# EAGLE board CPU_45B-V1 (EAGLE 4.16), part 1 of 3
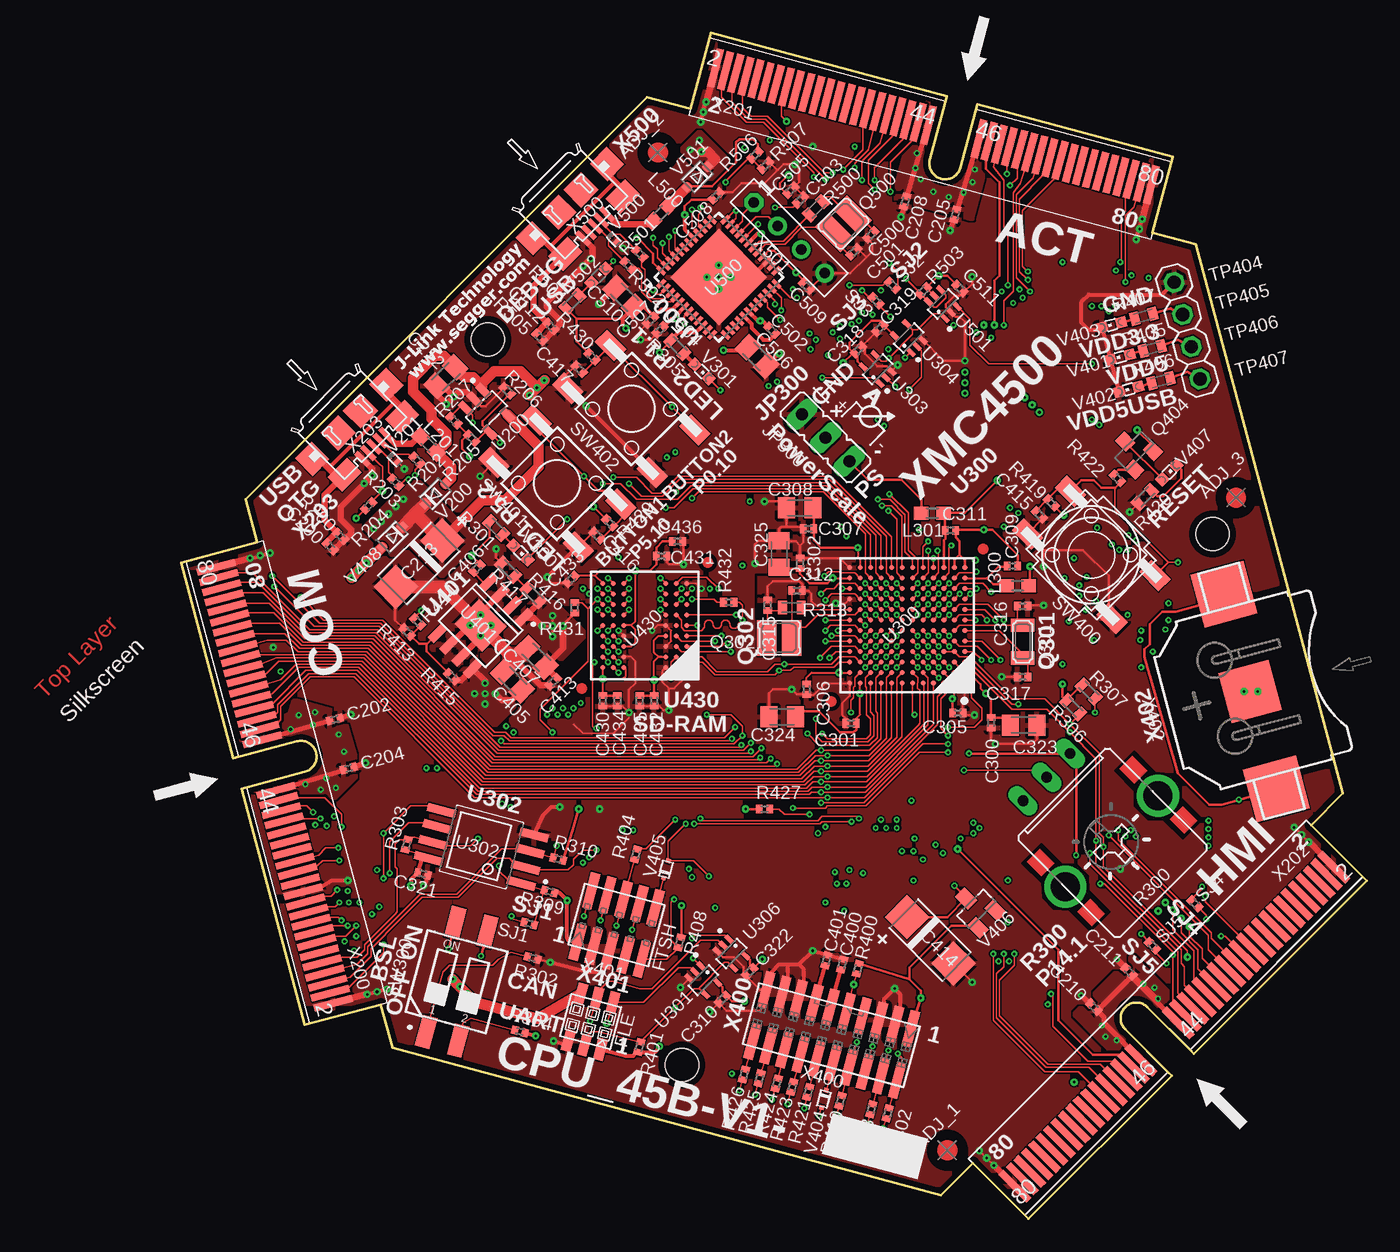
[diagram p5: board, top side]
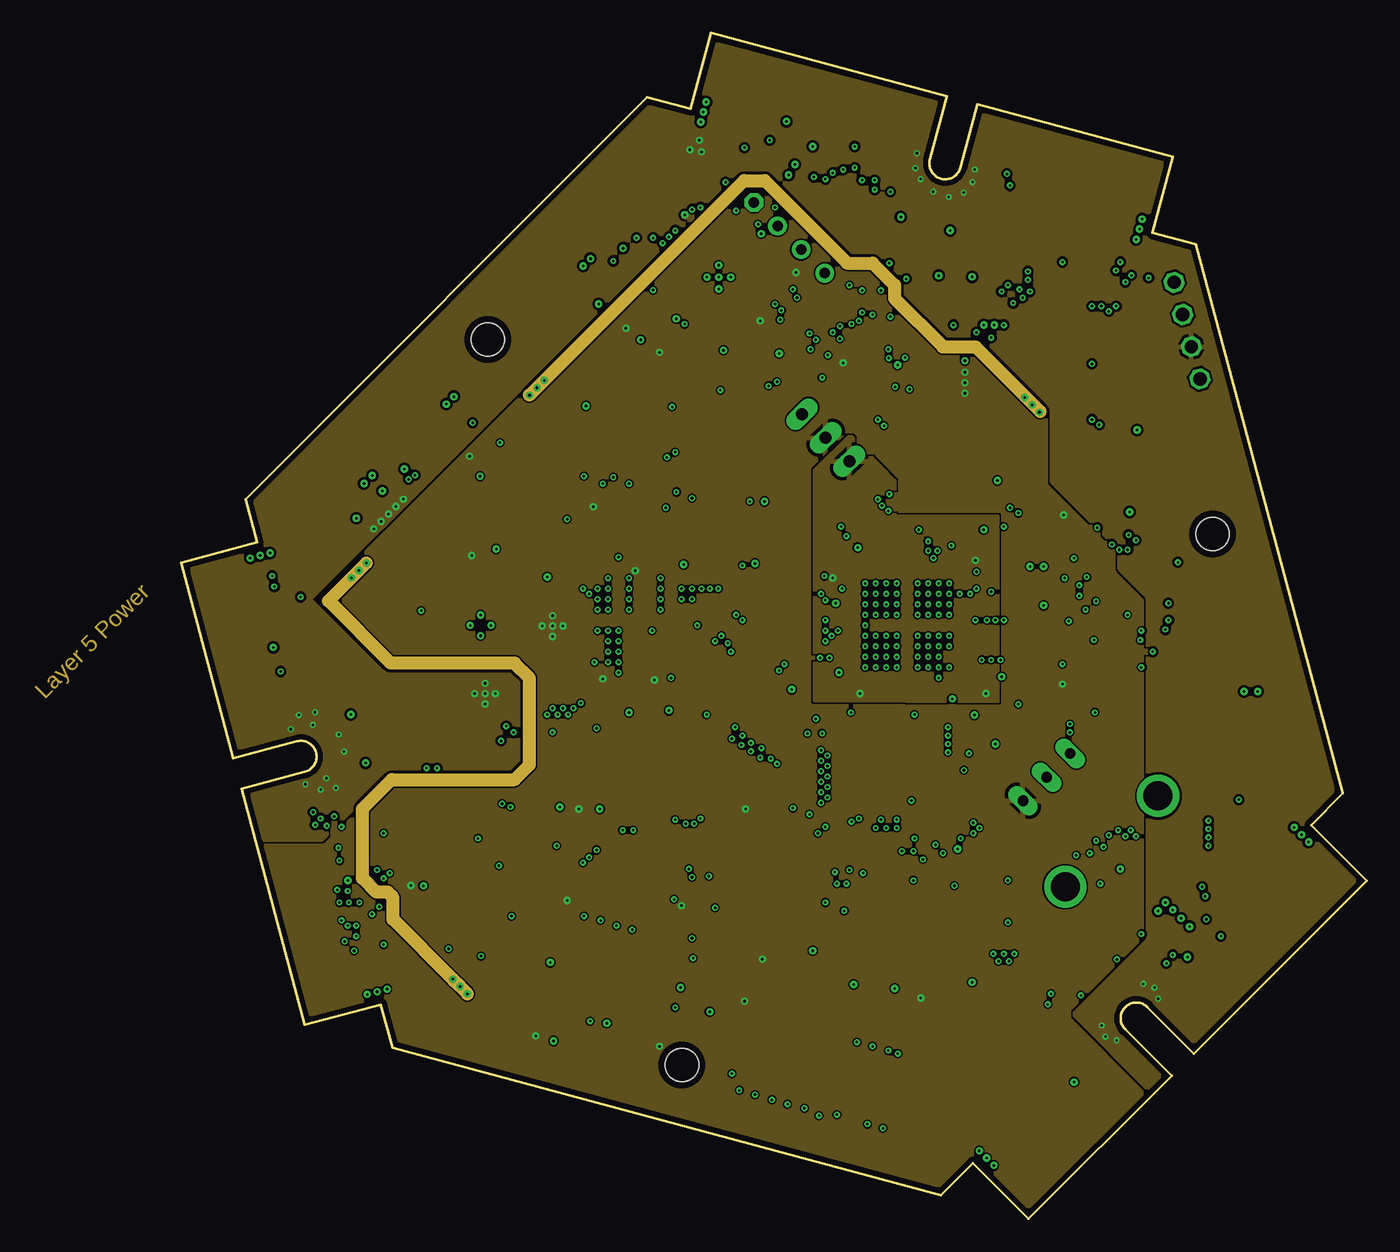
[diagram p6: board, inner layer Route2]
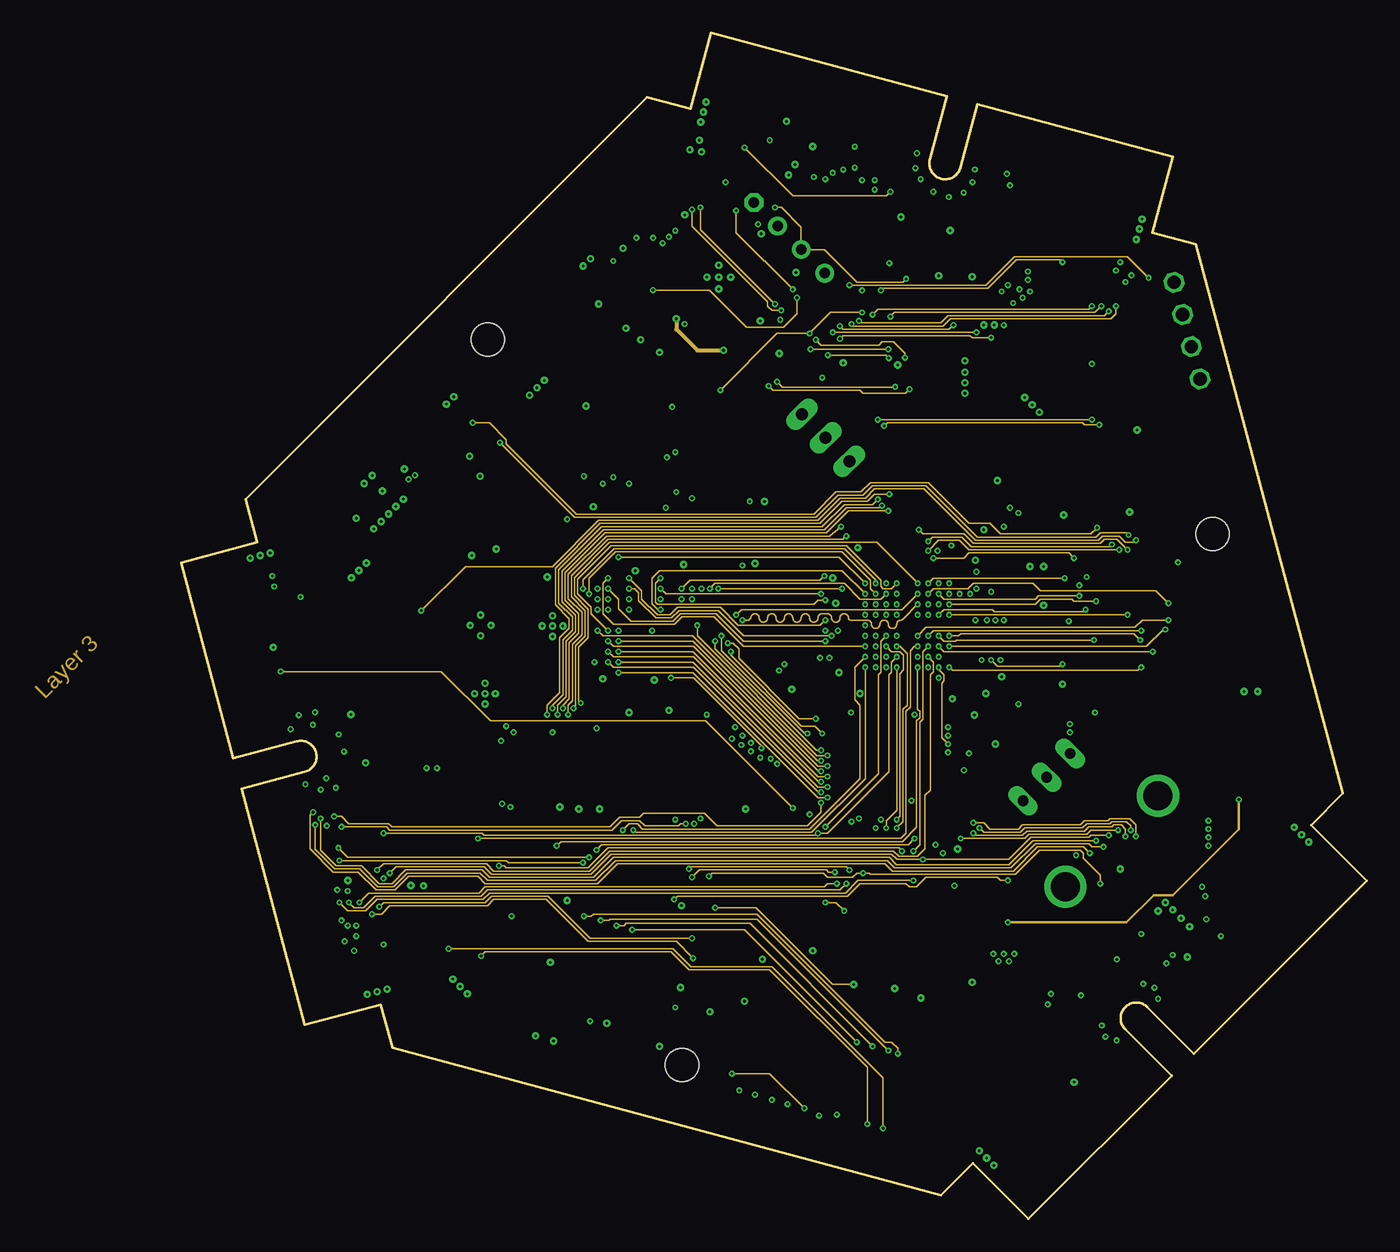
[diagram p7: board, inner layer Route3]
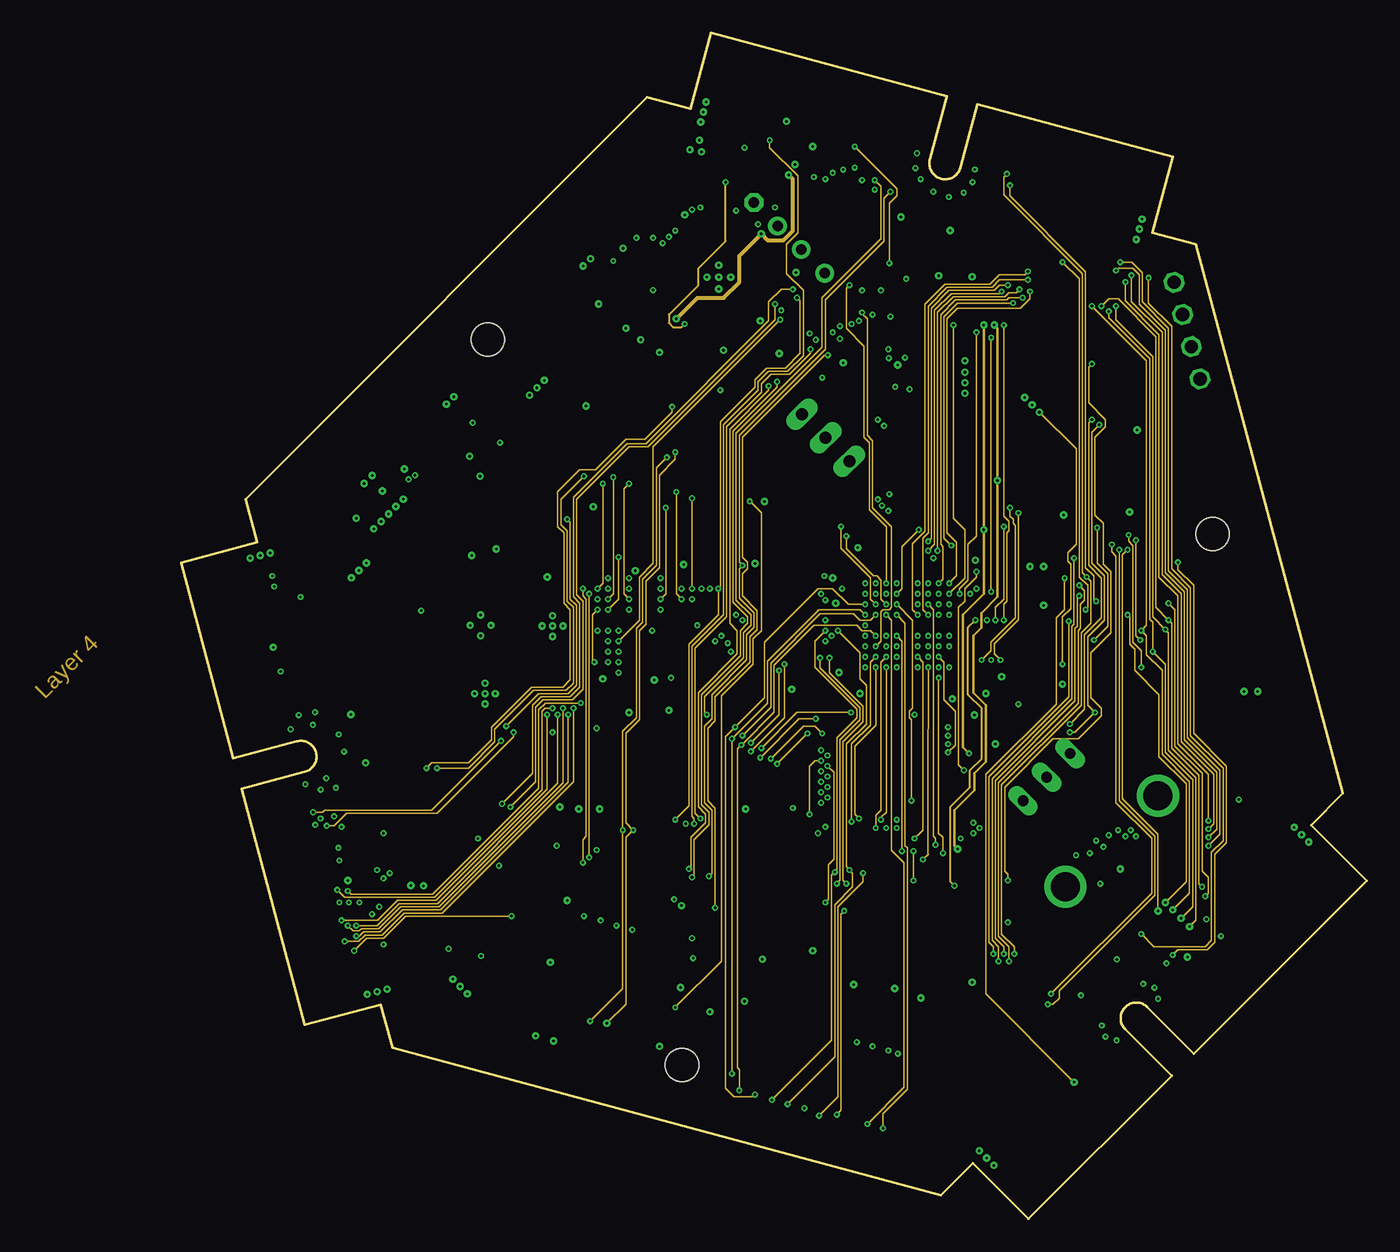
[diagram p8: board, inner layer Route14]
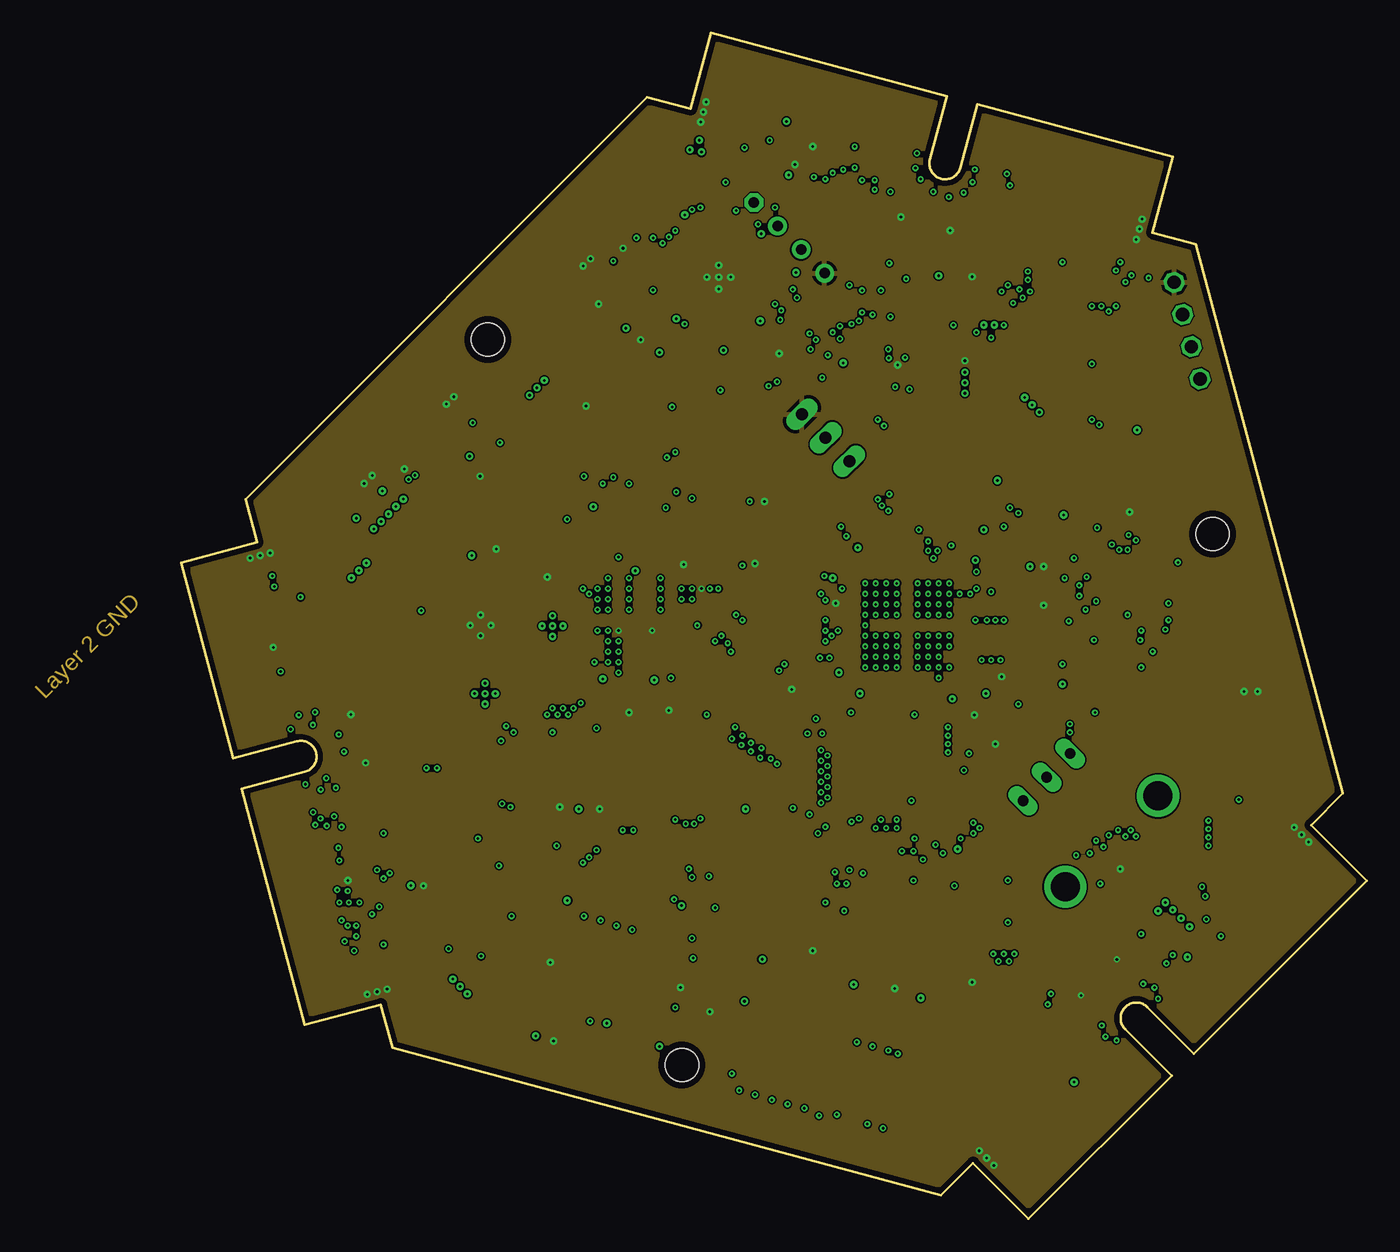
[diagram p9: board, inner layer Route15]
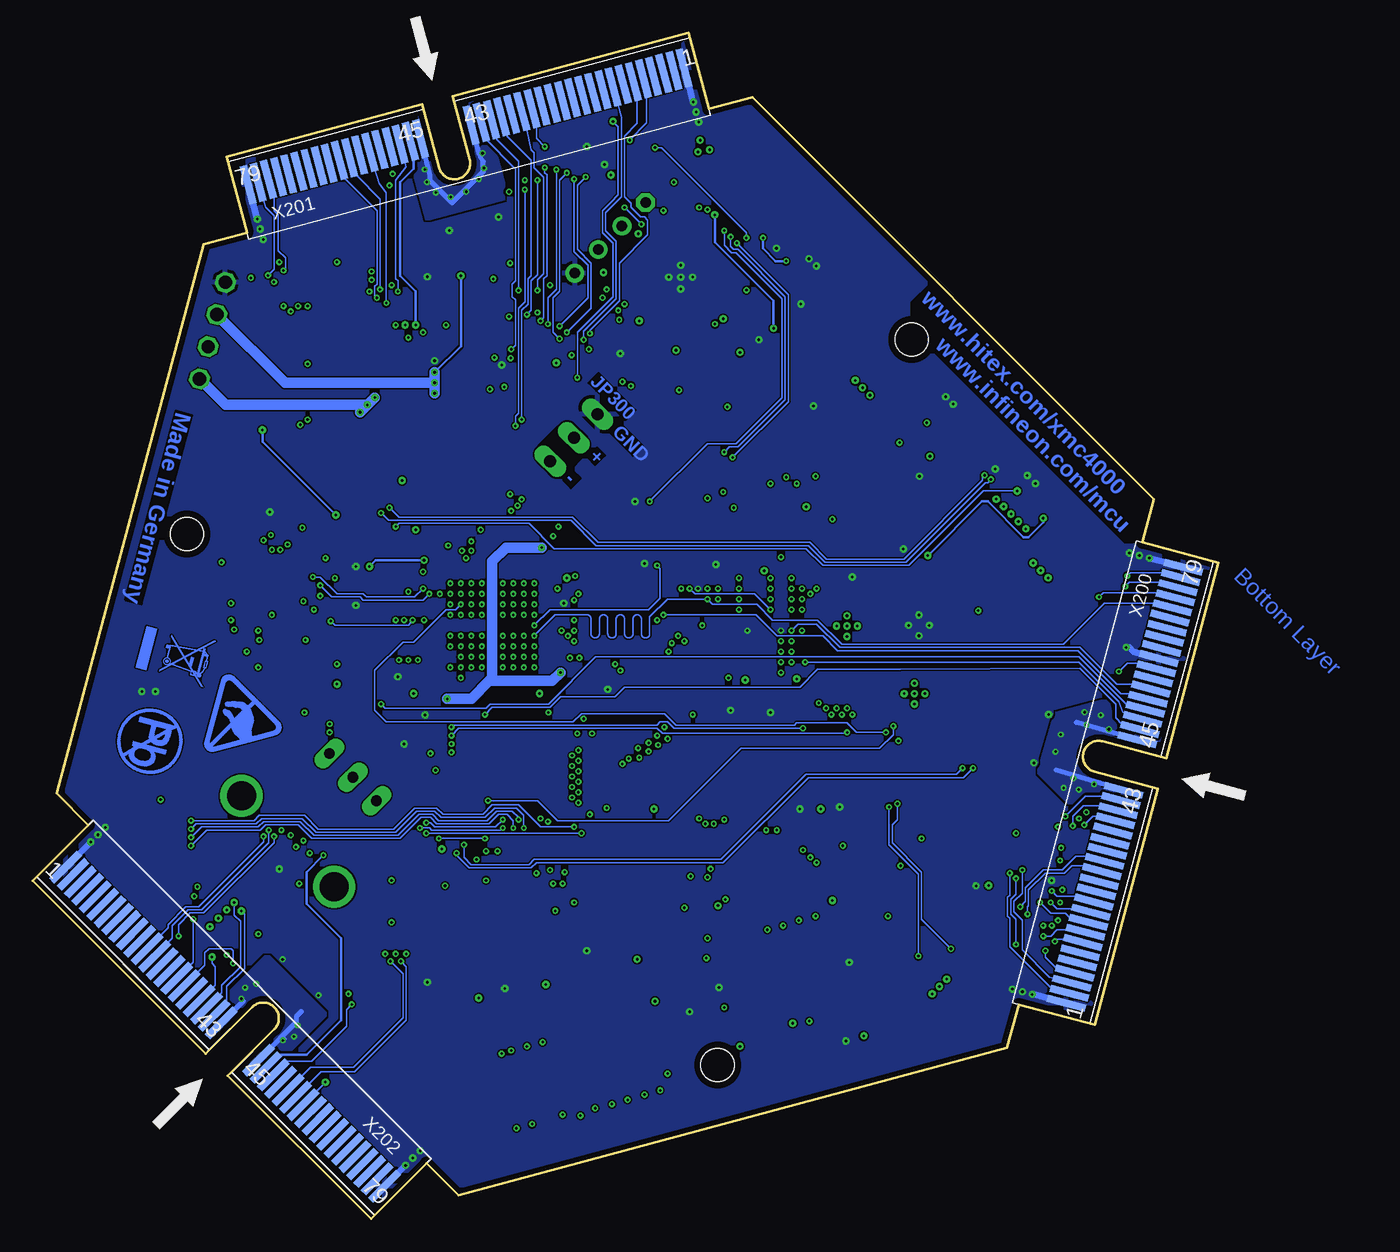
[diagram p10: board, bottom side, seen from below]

Size 90.38 x 90.38 mm. Coordinates in mm from the lower left corner, seen from the top.
Outline: 15.23,16.34 16.12,13.03 57.94,1.82 60.36,4.24
Outline: 5.79,51.54 4.91,54.85 35.53,85.47 38.84,84.58
Outline: 74.04,75.15 77.35,74.26 88.56,32.44 86.14,30.02
Copper layers (1*2+3*14+15*16): Top 0.035mm / dielectric 0.27mm / Route2 0.035mm / dielectric 0.27mm / Route3 0.035mm / dielectric 0.27mm / Route14 0.035mm / dielectric 0.27mm / Route15 0.035mm / dielectric 0.27mm / Bottom 0.035mm
Design rules "default": minimum track width 0.12mm, minimum drill 6mil, track to track 0.119mm, track to pad 0.12mm, pad to pad 0.12mm, via to via 0.12mm, smd to smd 5mil, copper to edge 0.5mm, drill to drill 8mil, minimum pad ring 10mil, minimum via ring 0.125mm, stop-mask expansion 4mil, vias tented up to drill 0.2mm, thermal gap 10mil
Holes 2.54 mm at 23.38,67 38.19,11.74 78.64,52.19
tRestrict: 2 lines
bRestrict: 6 lines
Milling: 9 lines

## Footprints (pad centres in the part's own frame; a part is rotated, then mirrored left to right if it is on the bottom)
C0402 = smd 0.5 x 0.65: 1 -0.4,0; 2 0.4,0
C0805K = smd 1.3 x 1.6: 1 -1,0; 2 1,0
SMC_C = smd 2.4 x 2.4: + -2.5,0; - 2.5,0
PS3_MIRROR_SW = drill 0.914 long: 1 0,0; 2 2.54,0; 3 -2.54,0
L1608 = smd 1.1 x 1: 1 -0.85,0; 2 0.85,0
FC-135 = smd 1 x 1.8: P$1 -1.25,0; P$2 1.25,0
32X25_2PAD = smd 1.5 x 2.7: 1 -0.95,0; 2 0.95,0
TO236 = smd 1 x 1.2: 1 -1,-1; 2 1,-1; 3 0,1
R0402 = smd 0.5 x 0.65: 1 -0.4,0; 2 0.4,0
POTI = drill 0.813 long: A -2.54,-6.992; E 2.54,-6.992; S 0,-6.992 | drill 2.2 round: P$1 -5,0.025; P$2 4.9,-0.075
R0603 = smd 0.67 x 1: 1 -0.715,0; 2 0.715,0
CTS-219-02 = smd 1.13 x 2.44: 1 -1.27,-4.3; 2 1.27,-4.3; 3 1.27,4.3; 4 -1.27,4.3
FSM2JSMA = smd 2.1 x 1.3: P -4.55,-2.3; P1 4.55,-2.3; S -4.55,2.3; S1 4.55,2.3
1X01 = drill 1.016 octagon: 1 0,0
SOT23-5L = smd 0.55 x 1.2: 1 -0.95,-1.3; 2 0,-1.3; 3 0.95,-1.3; 4 0.95,1.3; 5 -0.95,1.3
P/PG-LFBGA-144-9 = smd 0.37 x 0.37: A1 -4.4,4.4; A2 -3.6,4.4; A3 -2.8,4.4; A4 -2,4.4; A5 -1.2,4.4; A6 -0.4,4.4; A7 0.4,4.4; A8 1.2,4.4; A9 2,4.4; A10 2.8,4.4; A11 3.6,4.4; A12 4.4,4.4; B1 -4.4,3.6; B2 -3.6,3.6; B3 -2.8,3.6; B4 -2,3.6; B5 -1.2,3.6; B6 -0.4,3.6; B7 0.4,3.6; B8 1.2,3.6; B9 2,3.6; B10 2.8,3.6; B11 3.6,3.6; B12 4.4,3.6; C1 -4.4,2.8; C2 -3.6,2.8; C3 -2.8,2.8; C4 -2,2.8; C5 -1.2,2.8; C6 -0.4,2.8; C7 0.4,2.8; C8 1.2,2.8; C9 2,2.8; C10 2.8,2.8; C11 3.6,2.8; C12 4.4,2.8; D1 -4.4,2; D2 -3.6,2; D3 -2.8,2; D4 -2,2; D5 -1.2,2; D6 -0.4,2; D7 0.4,2; D8 1.2,2; D9 2,2; D10 2.8,2; D11 3.6,2; D12 4.4,2; E1 -4.4,1.2; E2 -3.6,1.2; E3 -2.8,1.2; E4 -2,1.2; E5 -1.2,1.2; E6 -0.4,1.2; E7 0.4,1.2; E8 1.2,1.2; E9 2,1.2; E10 2.8,1.2; E11 3.6,1.2; E12 4.4,1.2; F1 -4.4,0.4; F2 -3.6,0.4; F3 -2.8,0.4; F4 -2,0.4; F5 -1.2,0.4; F6 -0.4,0.4; F7 0.4,0.4; F8 1.2,0.4; F9 2,0.4; F10 2.8,0.4; F11 3.6,0.4; F12 4.4,0.4; G1 -4.4,-0.4; G2 -3.6,-0.4; G3 -2.8,-0.4; G4 -2,-0.4; G5 -1.2,-0.4; G6 -0.4,-0.4; G7 0.4,-0.4; G8 1.2,-0.4; G9 2,-0.4; G10 2.8,-0.4; G11 3.6,-0.4; G12 4.4,-0.4; H1 -4.4,-1.2; H2 -3.6,-1.2; H3 -2.8,-1.2; H4 -2,-1.2; H5 -1.2,-1.2; H6 -0.4,-1.2; H7 0.4,-1.2; H8 1.2,-1.2; H9 2,-1.2; H10 2.8,-1.2; H11 3.6,-1.2; H12 4.4,-1.2; J1 -4.4,-2; J2 -3.6,-2; J3 -2.8,-2; J4 -2,-2; J5 -1.2,-2; J6 -0.4,-2; J7 0.4,-2; J8 1.2,-2; J9 2,-2; J10 2.8,-2; J11 3.6,-2; J12 4.4,-2; K1 -4.4,-2.8; K2 -3.6,-2.8; K3 -2.8,-2.8; K4 -2,-2.8; K5 -1.2,-2.8; K6 -0.4,-2.8; K7 0.4,-2.8; K8 1.2,-2.8; K9 2,-2.8; K10 2.8,-2.8; K11 3.6,-2.8; K12 4.4,-2.8; L1 -4.4,-3.6; L2 -3.6,-3.6; L3 -2.8,-3.6; L4 -2,-3.6; L5 -1.2,-3.6; L6 -0.4,-3.6; L7 0.4,-3.6; L8 1.2,-3.6; L9 2,-3.6; L10 2.8,-3.6; L11 3.6,-3.6; L12 4.4,-3.6; M1 -4.4,-4.4; M2 -3.6,-4.4; M3 -2.8,-4.4; M4 -2,-4.4; M5 -1.2,-4.4; M6 -0.4,-4.4; M7 0.4,-4.4; M8 1.2,-4.4; M9 2,-4.4; M10 2.8,-4.4; M11 3.6,-4.4; M12 4.4,-4.4
SC70-5L = smd 0.35 x 0.8: 1 -0.65,-0.85; 2 0,-0.85; 3 0.65,-0.85; 4 0.65,0.85; 5 -0.65,0.85
SO08W = smd 2.2 x 0.635: 1 -3.651,1.905; 2 -3.651,0.635; 3 -3.651,-0.635; 4 -3.651,-1.905; 5 3.651,-1.905; 6 3.651,-0.635; 7 3.651,0.635; 8 3.651,1.905
PG-DSO-8-27_NO-PASTE = smd 0.65 x 1.51: 1 -1.905,-2.745; 2 -0.635,-2.745; 3 0.635,-2.745; 4 1.905,-2.745; 5 1.905,2.745; 6 0.635,2.745; 7 -0.635,2.745; 8 -1.905,2.745 | smd 3 x 2.65: 9 0,0
VFBGA54-6X9_8MMX8MM = smd 0.4 x 0.4: A1 -3.2,3.2; A2 -2.4,3.2; A3 -1.6,3.2; A7 1.6,3.2; A8 2.4,3.2; A9 3.2,3.2; B1 -3.2,2.4; B2 -2.4,2.4; B3 -1.6,2.4; B7 1.6,2.4; B8 2.4,2.4; B9 3.2,2.4; C1 -3.2,1.6; C2 -2.4,1.6; C3 -1.6,1.6; C7 1.6,1.6; C8 2.4,1.6; C9 3.2,1.6; D1 -3.2,0.8; D2 -2.4,0.8; D3 -1.6,0.8; D7 1.6,0.8; D8 2.4,0.8; D9 3.2,0.8; E1 -3.2,0; E2 -2.4,0; E3 -1.6,0; E7 1.6,0; E8 2.4,0; E9 3.2,0; F1 -3.2,-0.8; F2 -2.4,-0.8; F3 -1.6,-0.8; F7 1.6,-0.8; F8 2.4,-0.8; F9 3.2,-0.8; G1 -3.2,-1.6; G2 -2.4,-1.6; G3 -1.6,-1.6; G7 1.6,-1.6; G8 2.4,-1.6; G9 3.2,-1.6; H1 -3.2,-2.4; H2 -2.4,-2.4; H3 -1.6,-2.4; H7 1.6,-2.4; H8 2.4,-2.4; H9 3.2,-2.4; J1 -3.2,-3.2; J2 -2.4,-3.2; J3 -1.6,-3.2; J7 1.6,-3.2; J8 2.4,-3.2; J9 3.2,-3.2
QFN-48-7X7 = smd 0.8 x 0.3: 1 -3.45,2.75; 2 -3.45,2.25; 3 -3.45,1.75; 4 -3.45,1.25; 5 -3.45,0.75; 6 -3.45,0.25; 7 -3.45,-0.25; 8 -3.45,-0.75; 9 -3.45,-1.25; 10 -3.45,-1.75; 11 -3.45,-2.25; 12 -3.45,-2.75; 25 3.45,-2.75; 26 3.45,-2.25; 27 3.45,-1.75; 28 3.45,-1.25; 29 3.45,-0.75; 30 3.45,-0.25; 31 3.45,0.25; 32 3.45,0.75; 33 3.45,1.25; 34 3.45,1.75; 35 3.45,2.25; 36 3.45,2.75 | smd 0.3 x 0.8: 13 -2.75,-3.475; 14 -2.25,-3.475; 15 -1.75,-3.475; 16 -1.25,-3.475; 17 -0.75,-3.475; 18 -0.25,-3.475; 19 0.25,-3.475; 20 0.75,-3.475; 21 1.25,-3.475; 22 1.75,-3.475; 23 2.25,-3.475; 24 2.75,-3.475; 37 2.75,3.475; 38 2.25,3.475; 39 1.75,3.475; 40 1.25,3.475; 41 0.75,3.475; 42 0.25,3.475; 43 -0.25,3.475; 44 -0.75,3.475; 45 -1.25,3.475; 46 -1.75,3.475; 47 -2.25,3.475; 48 -2.75,3.475 | smd 5.2 x 5.2: EPAD 0,0
SC70-6L = smd 0.35 x 0.8: 1 -0.65,-0.85; 2 0,-0.85; 3 0.65,-0.85; 4 0.65,0.85; 5 0,0.85; 6 -0.65,0.85
SOD323-R = smd 0.6 x 0.6: A 1.1,0; C -1.1,0
TSLP-3-1 = smd 0.225 x 0.35: 1 0.113,-0.475; 2 0.487,-0.475 | smd 0.6 x 0.35: 3 0.3,0.175
CHIPLED_0603 = smd 0.8 x 0.8: A 0,-0.75; C 0,0.75
SC79 = smd 0.35 x 0.35: 1 -0.675,0; 2 0.675,0
SOT23-3 = smd 1 x 1.4: 1 -0.95,-1.1; 2 0.95,-1.1; 3 0,1.1
HSEC8_MATING-CARD_80 = smd 0.55 x 3 bottom: 1 -18.8,-2.5; 3 -18,-2.5; 5 -17.2,-2.5; 7 -16.4,-2.5; 9 -15.6,-2.5; 11 -14.8,-2.5; 13 -14,-2.5; 15 -13.2,-2.5; 17 -12.4,-2.5; 19 -11.6,-2.5; 21 -10.8,-2.5; 23 -10,-2.5; 25 -9.2,-2.5; 27 -8.4,-2.5; 29 -7.6,-2.5; 31 -6.8,-2.5; 33 -6,-2.5; 35 -5.2,-2.5; 37 -4.4,-2.5; 39 -3.6,-2.5; 41 -2.8,-2.5; 43 -2,-2.5; 45 2,-2.5; 47 2.8,-2.5; 49 3.6,-2.5; 51 4.4,-2.5; 53 5.2,-2.5; 55 6,-2.5; 57 6.8,-2.5; 59 7.6,-2.5; 61 8.4,-2.5; 63 9.2,-2.5; 65 10,-2.5; 67 10.8,-2.5; 69 11.6,-2.5; 71 12.4,-2.5; 73 13.2,-2.5; 75 14,-2.5; 77 14.8,-2.5; 79 15.6,-2.5 | smd 0.55 x 3: 2 -18.8,-2.5; 4 -18,-2.5; 6 -17.2,-2.5; 8 -16.4,-2.5; 10 -15.6,-2.5; 12 -14.8,-2.5; 14 -14,-2.5; 16 -13.2,-2.5; 18 -12.4,-2.5; 20 -11.6,-2.5; 22 -10.8,-2.5; 24 -10,-2.5; 26 -9.2,-2.5; 28 -8.4,-2.5; 30 -7.6,-2.5; 32 -6.8,-2.5; 34 -6,-2.5; 36 -5.2,-2.5; 38 -4.4,-2.5; 40 -3.6,-2.5; 42 -2.8,-2.5; 44 -2,-2.5; 46 2,-2.5; 48 2.8,-2.5; 50 3.6,-2.5; 52 4.4,-2.5; 54 5.2,-2.5; 56 6,-2.5; 58 6.8,-2.5; 60 7.6,-2.5; 62 8.4,-2.5; 64 9.2,-2.5; 66 10,-2.5; 68 10.8,-2.5; 70 11.6,-2.5; 72 12.4,-2.5; 74 13.2,-2.5; 76 14,-2.5; 78 14.8,-2.5; 80 15.6,-2.5
ZX62-AB-5PA_MICRO-USB = smd 0.4 x 1.35: 1 -1.3,1.45; 2 -0.65,1.45; 3 0,1.45; 4 0.65,1.45; 5 1.3,1.45 | smd 2.1 x 1.6: S1 -3.1,1.35; S2 3.1,1.35 | smd 1.8 x 1.9: S3 -4,-1.25; S4 4,-1.25 | smd 1.9 x 1.9: S5 -1.2,-1.25; S6 1.2,-1.25
FTSH-110-01-L-DV-K-P = smd 0.737 x 2.794: 1 -5.715,-2.032; 2 -5.715,2.032; 3 -4.445,-2.032; 4 -4.445,2.032; 5 -3.175,-2.032; 6 -3.175,2.032; 7 -1.905,-2.032; 8 -1.905,2.032; 9 -0.635,-2.032; 10 -0.635,2.032; 11 0.635,-2.032; 12 0.635,2.032; 13 1.905,-2.032; 14 1.905,2.032; 15 3.175,-2.032; 16 3.175,2.032; 17 4.445,-2.032; 18 4.445,2.032; 19 5.715,-2.032; 20 5.715,2.032
XE3K_DM2+CTX = smd 0.737 x 2.794: C1 -2.54,-2.032; C2 -2.54,2.032; C3 -1.27,-2.032; C4 -1.27,2.032; C5 0,-2.032; C6 0,2.032; C7 1.27,-2.032; C8 1.27,2.032; C9 2.54,-2.032; C10 2.54,2.032 | smd 0.74 x 1.675: D1 1.27,-9.46; D2 1.27,-5.78; D3 0,-9.46; D4 0,-5.78; D5 -1.27,-9.46; D6 -1.27,-5.78
BK-885 = smd 4.17 x 4.17: 1+ -7.685,0; 2+ 7.685,0 | smd 3.96 x 3.96: - 0,0
MA04-1 = drill 0.8 pad 1.422 octagon: 1 -3.81,0 | drill 0.8 pad 1.422 round: 2 -1.27,0; 3 1.27,0; 4 3.81,0

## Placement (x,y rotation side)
ADJ_1  FIDUCIAL  [FIDUCIAL]  58.41,5.24 45 top
ADJ_2  FIDUCIAL  [FIDUCIAL]  36.35,81.26 45 top
ADJ_3  FIDUCIAL  [FIDUCIAL]  80.42,54.96 45 top
C200  100nF/0402  [C0402]  11.35,51.23 315 top
C202  100nF/0402  [C0402]  11.73,38.07 15 top
C204  100nF/0402  [C0402]  12.77,34.33 15 top
C205  100nF/0402  [C0402]  59.02,76.54 255 top
C208  100nF/0402  [C0402]  55.2,77.53 255 top
C210  100nF/0402  [C0402]  69.57,16.15 135 top
C211  100nF/0402  [C0402]  72.27,18.84 135 top
C212  4u7F/0805  [C0805K]  20.17,64.18 225 top
C213  100uF/T/10V/C  [SMC_C]  18.14,49.92 225 top
C300  100nF/0402  [C0402]  61.75,37.81 270 top
C301  100nF/0402  [C0402]  51.07,37.77 180 top
C302  100nF/0402  [C0402]  47.19,49.95 90 top
C305  100nF/0402  [C0402]  59.21,38.55 0 top
C306  100nF/0402  [C0402]  47.69,40.37 270 top
C307  100nF/0402  [C0402]  47.83,52.59 180 top
C308  10uF/10V/0805  [C0805K]  47.15,54.17 180 top
C309  100nF/0402  [C0402]  63.37,49.75 0 top
C310  100nF/0402  [C0402]  41.27,16.75 225 top
C311  100nF/0402  [C0402]  58.65,52.47 0 top
C312  15pF/0402  [C0402]  46.95,47.87 0 top
C315  15pF/0402  [C0402]  44.71,46.75 90 top
C316  15pF/0402  [C0402]  64.15,46.69 0 top
C317  15pF/0402  [C0402]  64.15,41.3 180 top
C318  100nF/0402  [C0402]  51.63,66.22 45 top
C319  100nF/0402  [C0402]  53.27,67.86 225 top
C321  100nF/0402  [C0402]  18.42,26.29 345 top
C322  100nF/0402  [C0402]  43.35,18.83 225 top
C323  10uF/10V/0805  [C0805K]  64.23,37.63 0 top
C324  10uF/10V/0805  [C0805K]  45.83,38.27 180 top
C325  10uF/10V/0805  [C0805K]  45.59,50.67 90 top
C400  100nF/0402  [C0402]  50.39,19.39 75 top
C401  100nF/0402  [C0402]  49.19,19.71 75 top
C405  10uF/10V/0805  [C0805K]  25.27,40.99 135 top
C406  10nF/0402  [C0402]  22.55,49.59 45 top
C407  10uF/10V/0805  [C0805K]  27.08,42.8 135 top
C413  100nF/0402  [C0402]  28.38,40.93 225 top
C414  100uF/T/10V/C  [SMC_C]  57.11,21.23 315 top
C415  10nF/0402  [C0402]  65.43,53.66 315 top
C416  100nF/0402  [C0402]  31.71,52.07 135 top
C417  100nF/0402  [C0402]  30.36,64.75 135 top
C430  100nF/0402  [C0402]  32.15,39.47 270 top
C431  100nF/0402  [C0402]  36.63,50.51 0 top
C432  100nF/0402  [C0402]  36.07,39.47 270 top
C433  100nF/0402  [C0402]  29.72,48.73 225 top
C434  100nF/0402  [C0402]  33.27,39.47 270 top
C435  100nF/0402  [C0402]  34.95,39.47 270 top
C436  100nF/0402  [C0402]  37.83,51.63 0 top
C500  15pF/0402  [C0402]  52.59,74.98 225 top
C501  15pF/0402  [C0402]  51.29,73.68 45 top
C502  100nF/0402  [C0402]  45.03,67.71 315 top
C503  no ass./10nF/0402  [C0402]  47.21,77.64 45 top
C504  100nF/0402  [C0402]  36.52,67.74 225 top
C505  100nF/0402  [C0402]  46.48,78.38 45 top
C506  10uF/10V/0805  [C0805K]  43.91,65.71 315 top
C507  100nF/0402  [C0402]  35.79,68.48 225 top
C508  100nF/0402  [C0402]  40.79,77.95 45 top
C509  100nF/0402  [C0402]  47.67,71.07 315 top
C510  10uF/10V/0805  [C0805K]  33.81,70.23 135 top
C511  100nF/0402  [C0402]  59.37,70.9 315 top
C512  100nF/0402  [C0402]  28.19,68.01 315 top
JP300  [PS3_MIRROR_SW]  49.14,59.53 315 top
L201  BLM18PG600  [L1608]  18.86,59.01 315 top
L300  BLM18PG600  [L1608]  63.77,48.25 0 top
L301  BLM18PG600  [L1608]  57.27,53.77 180 top
L500  BLM18PG600  [L1608]  36.58,76.62 225 top
Q301  32.768KHZ  [FC-135]  64.15,44 270 top
Q302  12MHZ/S/3.2X2.5  [32X25_2PAD]  45.59,44.27 0 top
Q404  BC858C  [TO236]  72.67,58.52 45 top
Q500  12MHZ/S/3.2X2.5  [32X25_2PAD]  50.49,75.83 45 top
R200  1M/0402  [R0402]  12.15,52.03 135 top
R202  33R/0402  [R0402]  17.98,57.81 315 top
R203  33R/0402  [R0402]  16.34,56.14 315 top
R204  10k/0402  [R0402]  14.29,54.34 225 top
R205  no ass./10k/0402  [R0402]  22.15,59.48 135 top
R206  10k/0402  [R0402]  24.87,63.1 315 top
R207  10k/0402  [R0402]  20.8,60.84 315 top
R300  POTI/10K/VERT  [POTI]  70.92,28.72 225 top
R301  680R/0603  [R0603]  24.02,52.64 135 top
R302  4k7/0402  [R0402]  26.79,19.89 165 top
R303  10k/0402  [R0402]  17.2,28.53 255 top
R304  4k7/0402  [R0402]  25.83,14.29 345 top
R305  680R/0603  [R0603]  37.82,66.44 135 top
R306  2k2/0603  [R0603]  67.99,38.99 135 top
R307  2k2/0603  [R0603]  69.19,40.19 135 top
R309  10k/0402  [R0402]  28.08,24.95 345 top
R310  10k/0402  [R0402]  28.75,27.42 345 top
R313  510R/0603  [R0603]  46.55,46.59 180 top
R400  10k/0402  [R0402]  51.59,19.07 75 top
R401  10k/0402  [R0402]  34.94,13.1 255 top
R402  33R/0402  [R0402]  53.87,8.05 255 top
R403  33R/0402  [R0402]  52.62,8.36 255 top
R404  no ass./33R/0402  [R0402]  34.67,27.78 75 top
R405  1k5/0603  [R0603]  74.04,66.33 15 top
R406  1k5/0603  [R0603]  74.7,63.88 15 top
R407  680R/0603  [R0603]  73.38,68.78 15 top
R408  10k/0402  [R0402]  37.99,21.07 75 top
R410  no ass./33R/0402  [R0402]  50.27,9 255 top
R413  no ass./10k/0402  [R0402]  17.23,44.72 315 top
R414  10k/0402  [R0402]  18.02,45.51 315 top
R415  270k/0402  [R0402]  20.63,41.33 315 top
R416  0R/0603  [R0603]  26.85,47.55 315 top
R417  no ass./0R/0603  [R0603]  24.93,49.47 315 top
R419  10K/0402  [R0402]  66.33,54.56 315 top
R420  2K2/0603  [R0603]  73.46,55.02 45 top
R421  33R/0402  [R0402]  47.81,9.68 255 top
R422  10K/0402  [R0402]  71.37,56.43 135 top
R423  33R/0402  [R0402]  46.59,10.04 255 top
R424  33R/0402  [R0402]  45.4,10.33 255 top
R425  33R/0402  [R0402]  44.1,10.72 255 top
R426  33R/0402  [R0402]  42.91,11.01 255 top
R427  no ass./4k7/0402  [R0402]  44.47,31.23 0 top
R429  10k/0402  [R0402]  32.68,53.04 135 top
R430  10k/0402  [R0402]  31.32,65.71 135 top
R431  10k/0402  [R0402]  30.01,46.56 270 top
R432  22R/0402  [R0402]  41.75,46.99 0 top
R500  510R/0603  [R0603]  48.4,77.02 45 top
R501  33R/0402  [R0402]  34.97,73.54 135 top
R502  33R/0402  [R0402]  34.09,72.66 135 top
R503  10k/0402  [R0402]  56.6,70.73 45 top
R504  680R/0603  [R0603]  29.85,69.89 45 top
R505  1M/0402  [R0402]  27.34,67.17 135 top
R506  4k7/0402  [R0402]  43.75,81.07 45 top
R507  10k/0402  [R0402]  44.55,80.27 225 top
SJ1  [R0402]  26.54,22.5 165 top
SJ2  [R0402]  54.23,71.15 315 top
SJ3  [R0402]  52.98,69.95 135 top
SJ4  [R0402]  77.27,24.03 315 top
SJ5  [R0402]  74.05,20.82 315 top
SW300  219-02  [CTS-219-02]  21.02,18.08 345 top
SW400  TMPS2-SMD  [FSM2JSMA]  69.39,50.6 135 top
SW401  TMPS2-SMD  [FSM2JSMA]  28.67,56.05 135 top
SW402  TMPS2-SMD  [FSM2JSMA]  34.33,61.71 135 top
TP404  no ass.  [1X01]  75.7,71.37 285 top
TP405  no ass.  [1X01]  76.35,68.92 285 top
TP406  no ass.  [1X01]  77.01,66.46 285 top
TP407  no ass.  [1X01]  77.67,64.01 285 top
U200  TPS2051BDBV  [SOT23-5L]  23.29,61.52 225 top
U300  XMC4500_LFBGA144  [P/PG-LFBGA-144-9]  55.35,45.23 180 top
U301  74LVC1G66DCK  [SC70-5L]  39.8,18.19 225 top
U302  S25FL032P0XMFI01  [SO08W]  22.9,28.35 165 top
U303  74LVC1G66DCK  [SC70-5L]  53.1,64.75 45 top
U304  74LVC1G66DCK  [SC70-5L]  55.47,67.12 45 top
U306  74LVC1G66DCK  [SC70-5L]  41.95,20.23 225 top
U401  IFX1763_PADNOP  [PG-DSO-8-27_NO-PASTE]  22.83,45.23 135 top
U430  IS42S16400F-7BL  [VFBGA54-6X9_8MMX8MM]  35.35,45.23 180 top
U500  XMC4200_QFN48  [QFN-48-7X7]  40.99,71.76 45 top
U501  NC7WZ07P6X  [SC70-6L]  58.07,69.71 45 top
U$180  [DIN_A5_L]  not placed on the board
V200  BAS3010A-03W  [SOD323-R]  19.38,55.24 45 top
V201  ESD8V0L2B-03L  [TSLP-3-1]  16.57,58.02 225 top
V300  LED-GE/D/0603  [CHIPLED_0603]  25.89,50.77 225 top
V301  LED-GE/D/0603  [CHIPLED_0603]  39.69,64.58 225 top
V401  LED-GN/D/0603  [CHIPLED_0603]  71.59,65.67 105 top
V402  LED-GN/D/0603  [CHIPLED_0603]  72.24,63.22 105 top
V403  LED-GN/D/0603  [CHIPLED_0603]  70.93,68.13 105 top
V404  BAT54-02V  [SC79]  49.01,9.15 255 top
V405  BAT54-02V  [SC79]  36.96,26.64 75 top
V406  BAV70  [SOT23-3]  60.63,23.63 45 top
V407  LED-RT/D/0603  [CHIPLED_0603]  75.33,56.88 315 top
V408  BAS3010A-03W  [SOD323-R]  16.1,51.96 225 top
V500  ESD8V0L2B-03L  [TSLP-3-1]  33.27,74.79 225 top
V501  BAS3010A-03W  [SOD323-R]  39.35,79.4 225 top
V502  LED-GN/D/0603  [CHIPLED_0603]  31.83,71.87 315 top
X200  HSEC8_MATING-CARD  [HSEC8_MATING-CARD_80]  4.3,33.94 105 top
X201  HSEC8_MATING-CARD  [HSEC8_MATING-CARD_80]  59.54,85.25 345 top
X202  HSEC8_MATING-CARD  [HSEC8_MATING-CARD_80]  76.36,11.75 225 top
X203  ZX62-AB-5PA  [ZX62-AB-5PA_MICRO-USB]  13.71,59.86 225 top
X400  S2*10/1.27SO  [FTSH-110-01-L-DV-K-P]  49.6,14.02 165 top
X401  XE3K_DM2+CTX  [XE3K_DM2+CTX]  33.19,22.4 345 top
X402  BK-885  [BK-885]  81.49,40.19 285 top
X500  ZX62-AB-5PA  [ZX62-AB-5PA_MICRO-USB]  30.52,76.67 225 top
X501  no ass.  [MA04-1]  46.37,74.76 315 top

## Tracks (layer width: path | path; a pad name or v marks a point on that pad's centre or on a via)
AGND  (via drill 0.2, 0.2 pad 0.55)
  Top 0.2: U300.M1 59.75,50.19 59.35,50.59 | U300.M2 58.95,50.19 59.35,50.59 | v68.23,27.71 68.23,34.99 67.75,35.47 67.75,35.46 R300.A 67.74,35.46 60.08,35.46 v60.07,35.47 | v61.19,52.51 | C309.2 63.77,50.57 61.83,52.51 v61.19,52.51 | v61.19,52.51 | 59.35,50.59 59.35,51.63 59.05,51.93 C311.2 59.05,52.51 59.03,52.51 | v61.19,52.51 59.03,52.51 | 59.03,52.51
  Route14 0.2: v61.19,68.11 v61.19,52.51 61.19,47.63 59.59,46.03 59.59,35.95 v60.07,35.47
  Bottom 0.12: X202.47 71.59,12.51
  Bottom 0.2: 71.64,12.51 71.59,12.51 69.51,12.51 66.87,15.15 66.87,21.39 69.51,24.03 69.51,26.43 v68.23,27.71 | v61.19,68.11 61.19,70.67 62.39,71.87 62.39,78.99 61.35,80.03 61.35,80.67 X201.47
COM_RXD  (via drill 0.2)
  Top 0.12: v39.03,19.87 v39.04,19.87 U301.1
  Route3 0.12: v39.03,19.87 37.75,21.15 31.03,21.15 27.83,24.35 23.83,24.35 23.35,23.87 15.91,23.87 15.27,23.23 v14.55,23.23
  Bottom 0.12: X200.27 8.87,26.43 10.31,26.91 11.19,26.91 11.75,26.35 13.19,26.35 14.47,25.07 14.47,23.87 14.55,23.79 v14.55,23.23
COM_TXD  (via drill 0.2)
  Top 0.12: U306.1 41.47,21.63 39.19,21.63 v38.96,21.4 v38.95,21.4 v38.95,21.39
  Route3 0.12: v15.11,23.79 15.43,24.11 23.19,24.11 23.67,24.59 27.99,24.59 31.19,21.39 v38.95,21.39 | v38.95,21.39 | v38.95,21.39 v38.95,21.4
  Bottom 0.12: X200.29 8.71,27.23 10.07,27.63 10.87,27.63 11.91,26.59 13.35,26.59 14.71,25.23 14.71,24.19 v15.11,23.79
COMDIS#  (via drill 0.2)
  Top 0.12: X401.D3 31.03,14.03 31.27,14.27 31.83,14.27 R401.1 v37.67,16.11 39.11,17.55 39.51,17.55 | U301.4 39.52,17.55 39.51,17.55 | U306.4 41.71,19.55 41.43,19.55 39.51,17.63 39.51,17.55 | U500.44 37.67,74.02 v37.67,75.31
  Route14 0.12: v37.67,16.11 41.19,19.63 41.19,39.87 43.59,42.27 43.59,44.19 44.23,44.83 44.23,53.79 v43.35,54.67
  Bottom 0.12: v43.35,54.67 38.95,59.07 36.79,59.07 33.27,62.59 33.27,70.11 36.79,73.63 37.11,73.63 37.67,74.19 v37.67,75.31
CS  (via drill 0.2)
  Top 0.12: U500.23 45.75,70.18 v45.75,69.23 | v38.95,76.91 | U500.40 38.95,75.57 v38.95,76.91
  Route3 0.12: v45.75,69.23 45.03,69.23 44.71,69.55 44.71,69.87 38.95,75.63 | v38.95,76.91 | 38.95,75.63 | 38.95,75.63 v38.95,76.91
DBG2PRES#  (via drill 0.2)
  Top 0.12: X401.C9 37.02,19.78 37.83,20.59 R408.1 37.35,21.22 37.35,24.11 v37.59,24.35 | v69.43,65.15 61.59,65.15 60.15,66.59 60.15,68.55 U501.3
  Route3 0.12: v37.59,24.35 37.83,24.59 50.79,24.59 51.75,25.55 55.27,25.55 55.51,25.31 56.07,25.31 56.79,26.03 62.23,26.03 62.47,25.79 v63.03,25.79
  Route14 0.12: v63.03,25.79 63.03,26.27 62.79,26.51 62.79,32.91 66.47,36.59 68.39,36.59 70.15,38.35 70.15,38.91 69.35,39.71 69.35,43.15 70.87,44.67 70.87,49.31 70.31,49.87 70.31,52.99 69.67,53.63 69.67,59.55 70.47,60.35 70.47,60.91 69.19,62.19 69.19,64.91 v69.43,65.15
DBGPRES#  (via drill 0.2, 0.2 pad 0.55)
  Top 0.12: X400.9 v51.27,17.87 51.51,18.67 R400.1 | U303.4 53.39,65.37 53.72,65.37 v53.95,65.59 55.76,67.4 55.76,67.76 | 55.76,67.76 U304.4 | 55.76,67.76 56.12,67.76 57.35,68.99 57.87,68.99 U501.1
  Route3 0.12: v51.27,17.87 49.67,17.87 43.83,23.71 v40.71,23.71 | v49.31,65.82 53.72,65.82 v53.95,65.59
  Route14 0.12: v40.71,23.71 40.71,31.31 40.15,31.87 40.15,37.39 40.71,37.95 40.71,39.79 43.35,42.43 43.35,44.35 43.91,44.91 43.91,46.35 42.79,47.47 42.79,49.15 43.19,49.55 43.19,50.03 42.79,50.43 42.79,59.55 49.06,65.82 v49.31,65.82
DEBUG_LED#  (via drill 0.2)
  Top 0.2: U500.48 35.99,72.87 35.99,73.55 34.79,74.75 v34.71,74.75 | V502.C 32.39,72.43 v32.95,72.99 | v34.71,74.75
  Bottom 0.2: v32.95,72.99 33.75,72.99 34.71,73.95 v34.71,74.75 | v34.71,74.75
DSD_DIN3A  (via drill 0.2, 0.2 pad 0.55)
  Top 0.12: 46.15,86.27 46.31,86.91 | 46.15,86.27 45.99,85.63 | v46.15,83.63 45.75,84.03 45.75,84.83 46.15,86.27 | 46.15,86.27 X201.16 | U303.1 52.81,64.11 v48.87,64.11
  Bottom 0.12: v46.15,83.63 45.75,83.23 45.75,78.03 46.31,77.47 46.95,76.83 46.95,75.15 46.15,74.35 46.15,70.27 48.87,67.55 v48.87,64.11
DSD_MCLK3A  (via drill 0.2)
  Top 0.12: U304.1 v55.19,65.63
  Route3 0.12: v48.39,66.99 48.79,66.59 53.19,66.59 53.43,66.83 54.31,66.83 55.19,65.95 v55.19,65.63
  Bottom 0.12: 46.31,86.91 45.99,85.71 X201.15 46.15,86.27 45.51,83.95 45.51,77.87 46.71,76.67 46.71,75.31 45.91,74.51 45.91,70.11 48.39,67.63 v48.39,66.99
GND  (via drill 0.2, 0.2 pad 0.55)
  Top 0.12: U401.9 22.84,45.26 22.81,45.26 22.97,45.1 | U430.J1 39.27,48.43 v39.67,48.03 | 22.79,46.11 22.79,46.19 | 22.79,46.11 22.81,46.09 | v22.83,46.02 22.79,46.06 22.79,46.11 | U500.EPAD 40.95,71.71 40.95,71.72 U500.EPAD | 29.91,37.71 30.63,36.99 32.95,36.99 34.15,38.19 v34.15,38.59 | 48.07,47.07 48.39,46.75 49.75,46.75 v49.91,46.91 | v49.91,46.91 | v49.91,46.91
  Top 0.16: U300.J12 50.63,46.91 v49.91,46.91 | V201.3 16.5,57.69 v17.03,57.15 | U430.D7 v33.35,44.83 | U430.A3 36.71,41.79 36.71,40.91 37.19,40.43 | 37.19,40.43 v37.19,38.75 v37.19,38.76 | 37.19,40.43 37.59,40.43 38.55,41.39 U430.A1 | U430.C3 37.35,44.03 37.35,44.83 U430.E3 36.31,45.23 v35.91,44.83 | U430.B7 34.31,42.83 34.63,42.51 34.63,40.83 34.15,40.35 v34.15,38.59 | 50.23,50.35 U300.M12 | U300.A1 59.75,39.71 59.61,39.57 C305.2 | C301.2 50.67,38.15 50.39,38.43 50.39,39.31 50.95,39.87 U300.A12 49.11,40.83 48.23,39.95 47.67,39.95 C306.2 | v34.15,38.59
  Top 0.2: X201.80 73.91,78.51 | C213.- 16.33,48.11 16.33,45.63 R413.1 | R417.1 24.02,50.38 v24.02,51.06 | U200.2 22.89,61.92 23.23,61.92 24.64,63.33 R206.1 | V500.3 33.19,74.43 33.23,74.43 v33.69,73.97 | R302.1 v28.15,19.55 | U306.3 41.31,19.95 42.15,19.95 42.87,19.23 42.87,18.75 C322.2 44.15,17.47 44.63,17.47 | X400.19 44.15,15.87 41.59,15.87 C310.2 v40.31,15.79 | U301.3 38.07,17.66 v38.07,17.63 | 50.23,50.35 C302.2 47.19,51.31 | 47.19,51.31 46.87,51.63 45.59,51.63 C325.2 | 47.19,51.31 47.43,51.55 C307.2 47.43,52.67 47.35,52.75 46.15,52.75 C308.2 46.15,54.67 v44.47,54.67 | C325.2 45.59,52.59 45.75,52.75 46.15,52.75 | v43.75,49.95 43.75,51.39 44.03,51.67 C325.2 | C317.2 v62.55,41.31 | 64.55,46.67 C316.2 64.55,46.75 v65.75,46.75 | v60.47,38.39 | v60.47,38.39 | C305.2 59.77,38.39 v60.47,38.39 | C323.2 65.23,36.55 64.87,36.19 v62.07,36.19 | v62.07,36.19 | C300.2 61.75,36.51 v62.07,36.19 | C324.2 44.83,40.07 45.11,40.35 v46.55,40.35 | v46.55,40.35 | C306.2 46.93,39.97 v46.55,40.35 | v81.03,40.19 X402.- v82.07,40.19 | v81.03,40.19 | v5.27,50.35 X200.80 | C319.2 C318.2 52.13,66.27 52.14,65.93 53.1,64.97 53.79,64.97 U303.3 v54.63,65.07 | v37.19,38.75 36.79,38.75 36.47,39.07 C432.2 C435.2 | v27.91,48.91 27.83,48.91 28.3,48.45 C433.2 | C507.2 35.03,67.72 v35.03,66.99 35.77,66.99 C504.2 | v60.31,71.79 60.31,71.27 C511.2 59.35,70.35 58.95,70.35 58.31,69.71 58.31,69.47 U501.2 59.03,68.75 59.35,68.75 59.75,68.35 v59.75,65.39 58.12,65.39 U304.3 | SW401.S 30.3,51.23 C416.2 | C417.2 29.06,64.01 29.06,63.78 | SW402.S1 29.46,63.27 29.45,63.27 29.45,63.39 29.06,63.78 | 64.52,52.19 64.53,52.18 SW400.S1 | 64.52,52.19 C415.2
  Top 0.2: C500.2 52.7,74.31 52.7,73.74 52.25,73.29 | 49.08,72.04 | 49.08,72.04 X501.4 49.11,72.06 49.11,72.03 47.95,70.87 C509.2 | 52.25,73.29 51,72.04 49.08,72.04 | C501.2 52.25,73.29 | C503.2 C505.2 47.11,79.01 47.11,80.03 v46.79,80.35 | 43.42,71.71 43.13,71.42 42.24,71.42 v41.9,71.76 U500.EPAD 40.95,71.71 40.99,71.71 U500.EPAD | SW401.S1 v22.79,56.6 v22.79,56.59 | 29.06,63.78 30.87,61.97 v30.87,61.95 | v46.79,80.35 | v40.31,15.79 | v40.31,15.79 | 61.91,4.11 61.43,4.59 | 61.43,4.59 61.35,4.67 v61.4,4.64 61.43,4.59 | 61.43,4.59 v60.85,5.2 | v85.96,28.72 85.35,29.31 v85.4,29.28 84.87,29.87 v84.85,29.84 | v72.31,53.87 R420.1 | v65.75,49.71 65.75,50.96 | 64.52,52.19 65.75,50.96 | SW400.S 70.71,46.03 70.71,48.99 68.74,50.96 65.75,50.96 | U500.EPAD 41.03,71.76 41.03,71.79 U500.EPAD v40.99,70.85 | U500.EPAD 40.99,71.79 41.03,71.71 U500.EPAD v40.09,71.76 | U500.EPAD 40.95,71.76 40.95,71.79 40.99,71.83 v40.99,72.67 | v60.31,18.03 | C414.- v60.31,18.03 | v60.31,18.03 | C431.2 37.03,50.03 37.19,49.87 v38.31,49.87 38.31,51.55 C436.2 | C430.2 C434.2 33.67,39.07 v34.15,38.59 | v34.15,38.59 | v34.15,38.59 | C508.2 42.03,78.23 42.71,78.91 44.47,78.91 45.51,79.95 | 45.51,79.95 45.91,80.35 v46.79,80.35 | R507.1 45.44,79.95 45.51,79.95 | C315.2 44.71,48.19 45.11,48.59 47.11,48.59 47.35,48.35 | 47.35,48.35 | C312.2 47.83,47.87 48.07,47.63 48.07,47.07 | C312.2 | C312.2 | 47.35,48.35 C312.2
  Top 0.3: X200.24 10.71,25.31 11.51,25.79 v12.71,25.79 | 43.42,71.71 U500.27 | v18.48,25.38 18.55,25.39 C321.2 | U302.4 27.59,30.75 28.23,31.39 v28.87,31.39 | X401.C3 31.03,19.39 30.87,18.91 30.86,18.87 | X401.C5 32.31,19.07 32.07,18.83 31.03,18.83 30.86,18.87 | v28.15,19.55 30.86,18.87 | X401.D5 29.35,13.42 29.35,13.23 v28.39,13.55 | X400.3 54.79,16.11 54.79,17.15 v54.39,17.55 53.59,16.75 53.59,16.51 X400.5 | X400.17 46.23,18.43 46.23,19.39 | X400.15 47.43,18.11 47.43,19.07 47.11,19.39 | 49.27,20.11 C401.2 | 49.27,20.11 C400.2 | 46.23,19.39 45.59,19.39 45.03,18.83 44.63,17.47 X400.19 | 46.23,19.39 47.11,19.39 | 47.11,19.39 v48.15,20.43 49.27,20.11 | C510.2 33.06,70.94 v31.83,69.71 | v45.59,65.95 44.64,65 C506.2 | v22.83,46.02 22.87,46.02 22.87,46.03 22.83,45.99 v22.83,44.44 22.83,45.19 22.87,45.23 | v22.04,45.23 22.07,45.23 v23.62,45.23 22.87,45.23 | 22.87,45.23 U401.9 | v5.27,50.35 6.07,50.51 v6.03,50.55 v6.79,50.75 | 14.23,17.15 v14.95,17.31 15.67,17.55 v15.71,17.51 | v14.19,17.11 14.15,17.15 X200.2 | V402.C V401.C 70.23,67.95 V403.C 69.98,67.71 69.19,67.71 68.63,68.27 68.63,69.87 69.19,70.43 74.76,70.43 TP404.1 | v73.27,76.18 73.03,75.47 v73.06,75.42 72.79,74.67 v72.81,74.63 | v39.61,83.59 v39.83,84.35 v39.82,84.34 39.99,85.15 v40.03,85.1 39.99,85.07 X201.2 | SW402.S 35.92,56.9 v30.87,61.95 | v27.91,48.91 | SW401.S 30.21,51.21 v27.91,48.91
  Top 0.4: v54.87,76.35 C208.2 | v58.63,75.31 C205.2
  Top 0.406: C204.2 v14.07,34.75 | C202.2 v12.95,38.43 | C210.2 69.27,16.43 v68.6,17.04 | v68.6,17.04 | C211.2 71.99,19.15 v71.33,19.77
  Top 0.5: U401.7 22.81,44.3 22.81,45.18 22.84,45.18 U401.9 22.81,45.26 | 22.81,46.09 U401.3 | 20.57,43.82 21.85,45.1 v22.04,45.23 | 20.57,43.82 20.41,43.66 | U401.6 20.48,43.73 20.57,43.82 | C413.2 27.41,40.65 25.43,42.63 | X203.5 14.57,57.15 v14.57,56.66 v13.95,56.03 12.15,54.23 12.15,53.95 | v20.8,62.65 21.14,62.99 21.81,62.99 U200.2 | v20.8,62.65 v20.23,62.09 19.16,63.16 C212.2 19.72,63.73 v20.8,62.65 | X500.5 31.35,74.01 31.35,73.31 30.63,72.59 | v5.27,50.35 3.51,49.87 | X200.2 14.23,17.15 | v61.96,4.08 61.91,4.11 X202.80 | v73.27,76.18 v73.27,76.19 X201.80 | v40.03,85.1 40.07,85.15 X201.2 | v85.96,28.72 85.99,28.75 X202.2 | R200.1 12.47,51.79 C200.2 12.95,52.27 12.95,52.51 12.15,53.31 12.15,53.95 | 12.15,53.95 12.15,54.03 | R505.1 28.44,67.71 C512.2 28.87,68.12 28.87,68.51 27.91,69.47 27.91,69.86 v30.65,72.61
  Top 1: 24.76,41.72 C405.2 25.46,42.6 | C407.2 26.4,43.48 26.34,43.48 25.46,42.6 | 25.46,42.6 25.43,42.63 25.44,42.63 22.81,45.26 | C213.- 19.91,48.16 U401.9
  Bottom 0.2: 73.91,78.51 X201.80 73.99,78.75 | X202.2 87.91,26.83 | X200.2 | v5.27,50.35 X200.80
  Bottom 0.3: v40.03,85.1 40.07,85.15 X201.2
  Bottom 0.5: v5.27,50.35 3.75,49.95 | X200.61 6.47,43.23 6.79,43.55 v7.03,43.55 | v7.03,43.55 | v14.19,17.11 14.23,17.15 X200.2 | v61.96,4.08 61.91,4.11 X202.80 | v85.96,28.72 85.99,28.67 X202.2 | v73.27,76.18 v73.27,76.19 X201.80 | v40.03,85.1 40.07,85.07 40.71,87.71
  other vias: 48.15,81.71 71.59,26.67 31.21,73.17 40.99,71.76 31.91,31.23
  pour Route15 (rank 3): 89.8,26.04 85.84,30 88.31,32.47 77.21,74.12 73.81,74.97 75.23,80.34 60.73,84.23 59.6,79.99 arc-87 58.12,79.07 arc-88 56.92,80.84 57.98,85.01 40.44,89.68 38.96,84.23 35.56,85.22 5.16,54.82 6.07,51.35 0.7,49.94 4.59,35.44 8.69,36.57 arc-86 10.46,35.65 arc-101 9.4,33.89 5.3,32.76 9.96,15.08 15.27,16.56 15.48,16.63 16.26,13.17 57.91,2.07 60.38,4.54 64.34,0.58 74.95,11.19 71.83,14.3 arc-90 71.83,16.28 arc-94 73.89,16.21 76.93,13.17
  pour Bottom (rank 3): 89.8,26.04 85.84,30 88.31,32.47 77.21,74.12 73.81,74.97 75.23,80.34 60.73,84.23 59.6,79.99 arc-87 58.12,79.07 arc-88 56.92,80.84 57.98,85.01 40.44,89.68 38.96,84.23 35.56,85.22 5.16,54.82 6.07,51.35 0.78,49.94 4.67,35.44 8.69,36.57 arc-86 10.46,35.65 arc-101 9.4,33.89 5.3,32.76 9.96,15.08 15.27,16.56 15.48,16.63 16.26,13.17 57.91,2.07 60.38,4.54 64.34,0.58 74.95,11.19 71.83,14.3 arc-90 71.83,16.28 arc-94 73.89,16.21 76.93,13.17
  pour Top (rank 3): 89.8,26.04 85.84,30 88.31,32.47 77.21,74.12 73.81,74.97 75.23,80.34 60.73,84.23 59.6,79.99 arc-87 58.12,79.07 arc-88 56.92,80.84 57.98,85.01 40.44,89.68 38.96,84.23 35.56,85.22 5.16,54.82 6.07,51.35 0.7,49.94 4.59,35.44 8.69,36.57 arc-86 10.46,35.65 arc-101 9.4,33.89 5.3,32.76 9.96,15.08 15.27,16.56 15.48,16.63 16.26,13.17 57.91,2.07 60.38,4.54 64.34,0.58 74.95,11.19 71.83,14.3 arc-90 71.83,16.28 arc-94 73.89,16.21 76.93,13.17
HIB_IO_0  (via drill 0.2)
  Top 0.12: U200.3 22.23,61.23 v22.23,60.67 | v57.75,44.43 U300.F4
  Top 0.2: U200.3 21.54,61.92 21.53,61.92 21.31,61.92 R207.1
  Route3 0.12: v57.75,44.43 58.15,44.03 59.03,44.03 59.11,44.11 v69.59,44.11 | v69.83,52.67 69.35,52.19 62.47,52.19 61.67,52.99 60.07,52.99 56.95,56.11 52.55,56.11 51.83,55.39 49.91,55.39 48.23,53.71 30.15,53.71 24.79,59.07 24.79,59.39 23.51,60.67 v22.23,60.67
  Route14 0.12: v69.59,44.11 70.63,45.15 70.63,49.15 69.83,49.95 v69.83,52.67 | v69.83,52.67
HIB_IO_1  (via drill 0.2)
  Top 0.12: v58.55,44.43 | U300.F3 v58.55,44.43 | R414.1 17.75,45.79 v18.31,46.35
  Route3 0.12: v73.11,44.11 72.63,44.59 59.43,44.59 59.27,44.43 v58.55,44.43 | v72.79,51.71 72.63,51.55 71.99,51.55 71.51,52.03 70.23,52.03 69.91,51.71 60.55,51.71 56.63,55.63 52.87,55.63 52.15,54.91 50.23,54.91 48.55,53.23 31.83,53.23 28.31,49.71 21.67,49.71 v18.31,46.35
  Route14 0.12: v73.11,44.11 72.79,44.43 v72.79,51.71
N$1
  Top 0.12: R304.1 22.1,15.29 21.5,14.94 SW300.2
N$2
  Top 0.12: R302.2 25.17,20.32 24.21,19.77 23.75,19.31 20.47,19.31 19.99,18.83 SW300.1 18.69,14.29 18.69,14.3
N$3
  Top 0.16: U300.L1 61.43,48.83
  Top 0.2: L300.1 62.87,48.27 62.87,48.35 61.91,48.35 61.43,48.83 62.31,49.71 62.95,49.71 C309.1
N$4
  Top 0.5: X203.1 16.33,59.07 17.59,59.07 18.15,59.63 18.23,59.63 L201.1
N$5
  Top 0.12: 15.83,57.95 15.89,58.03 V201.2 | X203.3 14.95,58.83 15.83,57.95 | R203.1 16.06,56.51 16.15,56.59 15.83,56.91 15.83,57.95
N$6
  Top 0.12: V201.1 | X203.2 16.15,58.33 V201.1 | R202.1 17.67,58.09 17.59,58.03 17.35,58.27 V201.1
N$7
  Top 0.12: X400.12 48.55,12.11 R421.1
N$8
  Top 0.12: X400.14 47.35,12.59 R423.1
N$9
  Top 0.2: U401.5 18.7,43.79 | 18.7,43.79 18.7,43.25 R415.1 | 18.7,43.79 18.69,43.8 18.7,43.81 18.14,43.81 R413.2 R414.2
N$10  (via drill 0.2)
  Top 0.2: 80.71,31.95 79.35,31.55 78.39,31.55 75.99,33.95 73.43,42.83 73.43,43.39 73.83,43.79 73.83,45.31 74.79,46.27 75.83,46.27 79.51,47.31 X402.1+ | 80.71,31.95 X402.2+ | V406.2 62.1,23.53 v63.03,22.59 | 80.71,31.95 v80.63,31.95
  Route3 0.2: v63.03,22.59 72.07,22.59 74.15,24.67 75.59,24.67 80.63,29.71 v80.63,31.95
N$11
  Top 0.12: X400.16 46.07,12.83 R424.1
N$12
  Top 0.12: X400.18 44.87,13.23 R425.1
N$13
  Top 0.12: U300.H11 51.35,46.03 48.79,46.03 48.55,46.03 47.59,45.07 46.55,45.07 | Q302.2 46.55,45.07 | C312.1 | 46.55,45.07 C312.1 | C312.1
N$14
  Top 0.3: C400.1 50.31,18.99 X400.11
N$15
  Top 0.12: V405.1 36.79,25.95 X401.C10
N$16
  Top 0.12: X400.10 49.75,11.87 V404.1
N$17  (via drill 0.2)
  Top 0.12: R410.1 50.95,11.55 X400.8 v51.51,13.47 | v34.39,22.03 X401.C8
  Route3 0.12: v51.51,13.47 42.95,22.03 v34.39,22.03
N$18  (via drill 0.2)
  Top 0.12: R404.1 34.55,27.39 X401.C6 v33.19,22.35 | v52.71,13.15 X400.6
  Route3 0.12: v52.71,13.15 43.35,22.51 33.91,22.51 33.75,22.35 v33.19,22.35
N$19  (via drill 0.2)
  Top 0.12: X400.4 | X400.4 R403.1 | X400.4 53.75,12.19 v53.91,12.83 | v31.99,22.75 X401.C4
  Route3 0.12: v53.91,12.83 43.91,22.83 32.71,22.83 32.63,22.75 v31.99,22.75
N$20  (via drill 0.2)
  Top 0.12: R402.1 54.63,10.59 X400.2 54.95,11.87 54.95,12.27 v54.63,12.59 | v30.71,23.07 X401.C2
  Route3 0.12: v54.63,12.59 54.63,12.99 54.15,13.47 53.67,13.47 43.91,23.23 31.43,23.23 31.27,23.07 v30.71,23.07
N$21
  Top 0.3: C401.1 49.11,19.31 X400.13
N$22
  Top 0.2: V401.A 72.37,65.89 73.33,66.17 R405.1
N$23
  Top 0.12: X400.20 43.59,13.55 R426.1
N$24
  Top 0.2: V402.A 73.02,63.39 74.05,63.74 R406.1
N$25
  Top 0.2: V403.A 71.71,68.31 71.71,68.3 R407.1
N$26  (via drill 0.2 pad 0.55)
  Top 0.12: 14.15,49.98 14.15,49.95 v14.12,49.98 14.15,49.98
  Top 0.2: v12.99,48.85 13.53,49.39 13.59,49.39 | v13.56,49.42 13.59,49.39 | v14.12,49.98 13.59,49.45 13.59,49.39 | 21.02,17.94 21.03,17.95 v20.71,18.27
  Top 0.8: v12.99,48.85 v13.56,49.42 v14.12,49.98 V408.A | X401.D6 27.19,15.25 22.43,16.52 21.02,17.94 20.68,18.27
  Route2 0.2: v13.56,49.42 13.51,49.39 13.53,49.39 v14.12,49.98
  Route2 1: v14.12,49.98 11.24,47.1 15.98,42.35 25.43,42.35 26.55,41.23 26.55,34.59 25.43,33.47 16.05,33.47 13.83,31.25 13.83,25.95 14.87,24.91 15.75,24.91 16.15,24.51 16.15,22.83 v20.71,18.27 | v21.27,17.71 v21.83,17.15 v21.27,17.71 | v21.27,17.71 v20.71,18.27 | v21.27,17.71 v20.71,18.27
N$27
  Top 0.2: R420.2 74.42,55.07 74.87,55.07 76.23,56.43 76.23,57.07 V407.C
N$28
  Top 0.3: X203.S1 16.85,61.73 16.31,62.27 11.27,57.23 11.19,57.23
  Top 0.5: C200.1 11.83,52.27 R200.2 10.95,53.23 10.95,55.19 12.09,56.33 | 12.09,56.33 X203.S2 | 12.09,56.33 12.09,56.35 11.99,56.43 11.19,57.23 10.51,57.91 X203.S4 | X203.S1 16.85,61.15 17.19,61.47 15.65,63.01 X203.S3
N$29
  Top 0.5: L500.2 35.83,75.87 35.83,75.79 33.24,75.79 X500.1
N$30
  Top 0.3: X500.S1 33.67,78.43 33.11,78.99 | 33.03,79.07 33.03,78.99 28.11,74.07
  Top 0.5: R505.2 27.87,68.27 27.91,68.27 C512.1 26.87,69.33 26.87,71.11 X500.S2 29.11,73.53 28.87,73.31 28.11,74.07 27.45,74.73 X500.S4 | X500.S1 33.67,77.95 33.91,78.19 33.11,78.99 33.03,79.07 32.47,79.63 X500.S3
N$31
  Top 0.2: U401.4 23.35,48.44 23.34,48.45 23.12,48.45 C406.1
N$32  (via drill 0.2)
  Top 0.12: v51.91,70.75 | SJ3.2 52.43,70.23 v51.91,70.75
  Bottom 0.12: 53.11,84.43 53.27,85.07 | 53.11,84.43 X201.33 53.11,84.35 52.71,82.91 52.39,81.47 52.15,81.23 52.15,80.11 51.43,79.39 51.43,72.03 51.91,71.55 v51.91,70.75 | 53.11,84.43 52.95,83.79
N$33
  Top 0.3: R305.1 38.31,65.95 38.39,65.95 38.39,65.87 V301.A
N$34  (via drill 0.2)
  Top 0.16: U500.7 38.39,68.81 v38.39,68.19 | R507.2 43.43,80.83 43.47,80.83 R506.1 43.23,80.79 41.51,79.07 v41.51,78.99
  Route14 0.16: v38.39,68.19 38.15,67.95 37.51,67.95 37.19,68.27 37.19,68.91 39.43,71.15 39.43,72.43 41.51,74.51 v41.51,78.99
N$35
  Top 0.2: 74.84,56.35 V407.A | Q404.3 74.84,56.35 | 74.84,56.35 74.87,56.35
N$36
  Top 0.2: Q404.1 72.63,57.07 71.44,57.07 R422.2
N$37
  Top 0.12: X500.2 31.92,76.02 32.88,75.07 V500.1 33.47,75.04 R501.2
N$38
  Top 0.12: 63.57,45.25 Q301.P$1 63.75,45.23 C316.1 | 63.57,45.25 63.44,45.39 | U300.F2 59.35,45.23 63.59,45.23 63.59,45.24 63.57,45.25
N$39
  Top 0.2: R301.1 V300.A
N$40
  Top 0.12: C315.1 | R313.2 45.84,46.35 C315.1 | Q302.1 44.64,44.35 44.71,44.35 C315.1
N$41
  Top 0.12: X500.3 31.61,75.71 32.57,74.75 V500.2 32.59,74.17 R502.2
N$42
  Top 0.12: Q301.P$2 63.78,42.75 | 64.17,43.15 64.15,43.15 Q301.P$2 | 64.87,42.56 64.67,42.75 64.17,42.75 Q301.P$2 | Q301.P$2 64.15,43.07 62.39,44.83 U300.F1 | Q301.P$2 | Q301.P$2 | C317.1 64.55,42.75 Q301.P$2
N$43
  Top 0.12: U300.H12 48.47,46.43 47.43,46.43 R313.1 | R313.1 | R313.1
N$44
  Top 0.12: C500.1 51.63,76.51 51.19,76.51 | R500.2 49.25,77.87 49.51,77.87 50.87,76.51 51.19,76.51 | 51.19,76.51 Q500.2
N$45
  Top 0.12: 49.83,75.15 49.82,75.15 Q500.1 49.83,75.15 | 49.83,75.15 49.59,75.39 48.87,75.39 48.71,75.55 47.31,75.55 46.03,74.27 44.56,74.27 U500.29 | C501.1 49.83,74.57 49.83,75.15
N$46
  Top 0.12: R500.1 47.91,76.52 47.91,76.51 45.91,74.51 44.1,74.51 U500.30
N$47
  Top 0.2: 38.57,78.67 38.55,78.67 | V501.A 38.57,78.67 | 38.57,78.67 40.47,78.67 42.31,80.51 42.31,82.03 42.55,82.27 43.59,82.27 43.99,81.87 43.99,81.31 R506.2
  Top 0.8: V501.A 38.55,78.59 L500.1
N$48  (via drill 0.2)
  Top 0.12: v75.11,19.47 | v75.11,19.47 | SJ5.2 74.33,20.25 v75.11,19.47
  Bottom 0.12: 79.33,17.23 79.35,17.23 78.87,17.71 | 78.87,17.71 78.23,18.35 | 78.87,17.71 X202.33 | 78.87,17.71 77.27,19.31 77.27,20.27 76.95,20.59 75.27,20.59 75.11,20.43 v75.11,19.47 | v75.11,19.47 | v75.11,19.47
N$49  (via drill 0.2)
  Top 0.12: v25.19,23.07 | v25.19,23.07 25.35,22.83 SJ1.2
  Route14 0.12: v13.19,20.43 14.15,21.39 15.43,21.39 17.11,23.07 22.15,23.07 v25.19,23.07 | v25.19,23.07 | v25.19,23.07 | v25.19,23.07
  Bottom 0.12: X200.7 12.39,19.15 13.19,19.95 v13.19,20.43
N$50
  Top 0.3: U500.17 43.51,68.18 43.51,67.87 44.39,66.99 44.88,66.99 C502.2
N$51
  Top 0.2: 31.32,71.36 V502.A R504.2
N$52  (via drill 0.2)
  Top 0.12: SJ4.2 78.15,23.15 v78.15,22.83
  Bottom 0.12: X202.31 78.31,19.39 78.15,19.55 v78.15,22.83
N$53  (via drill 0.2)
  Top 0.12: SJ2.2 54.63,70.99 54.63,72.19 v53.99,72.83
  Route14 0.12: v53.99,72.83 53.99,77.39 54.55,77.95 54.55,78.51 v51.35,81.71
  Bottom 0.12: X201.31 52.39,84.59 51.99,83.15 51.99,82.35 v51.35,81.71
N$68
  Top 0.2: U401.2 26.34,47.84 R416.1 R417.2
OTG_FS_DM  (via drill 0.2)
  Top 0.12: U300.D1 60.39,43.23 v61.03,42.59 | v17.83,56.67 17.83,57.09 R202.2
  Route14 0.12: v61.03,42.59 61.75,43.31 61.75,43.95 63.59,45.79 63.59,52.83 63.43,52.99 63.43,53.31 63.19,53.55 v63.19,54.19 | v63.19,54.19
  Bottom 0.12: v17.83,56.67 17.99,56.51 17.99,56.27 23.99,50.27 29.87,50.27 31.15,51.55 47.31,51.55 49.23,53.47 62.47,53.47 v63.19,54.19 | v63.19,54.19
OTG_FS_DP  (via drill 0.2)
  Top 0.12: U300.E1 61.03,44.03 v62.47,42.59 | v17.35,56.35 17.12,56.35 R203.2
  Route14 0.12: v62.47,42.59 61.99,43.07 61.99,43.83 63.83,45.67 63.83,52.67 v63.83,53.79 | v63.83,53.79 | v63.83,53.79
  Bottom 0.12: v17.35,56.35 17.59,56.11 17.75,56.11 23.83,50.03 29.99,50.03 31.27,51.31 47.43,51.31 49.35,53.23 62.63,53.23 63.27,53.23 v63.83,53.79 | v63.83,53.79 | v63.83,53.79
P0.0  (via drill 0.2)
  Top 0.12: v57.75,42.03 U300.C4 | v58.47,36.19 56.55,36.19 52.07,31.71 v48.79,31.71
  Route3 0.12: v57.75,42.03 57.75,41.87 58.15,41.47 58.15,40.99 57.99,40.83 57.99,36.67 v58.47,36.19 | v48.79,31.71 48.79,30.99 47.75,29.95 40.87,29.95 39.91,30.91 35.27,30.91 34.95,30.59 33.43,30.59 32.71,29.87 16.07,29.87 15.83,30.11 12.79,30.11 12.23,30.67 v11.67,30.67 | v11.67,30.67 | v11.67,30.67
  Bottom 0.12: v11.67,30.67 10.15,32.19 8.87,32.19 X200.41
P0.1  (via drill 0.2)
  Top 0.12: v58.55,42.03 U300.C3 | U200.4 v24.31,59.15
  Top 0.2: 23.46,60 23.46,59.99 23.23,59.99 R205.1 | U200.4 23.46,60 | 23.46,60 23,60.46 23,60.79 25.1,62.88 R206.2
  Route3 0.12: v73.19,42.03 72.95,41.79 58.79,41.79 v58.55,42.03 | v72.23,52.11 72.07,52.27 70.07,52.27 69.75,51.95 60.71,51.95 56.79,55.87 52.71,55.87 51.99,55.15 50.07,55.15 48.39,53.47 29.99,53.47 v24.31,59.15
  Route14 0.12: v73.19,42.03 73.19,43.31 72.55,43.95 72.55,51.31 72.23,51.63 v72.23,52.11
P0.2  (via drill 0.2)
  Top 0.12: v33.35,41.63 U430.A8 | U300.A3 58.15,40.27 57.67,39.79 57.67,37.67 52.11,32.11 v49.27,32.11 22.39,32.11 13.19,41.31 9.83,41.31 7.59,39.07 7.59,38.03 7.27,37.71 5.99,37.31 X200.48
  Route3 0.12: 39.03,41.63 v33.35,41.63 | v49.27,32.11 48.55,32.11 39.03,41.63 | 39.03,41.63 | 39.03,41.63
P0.3  (via drill 0.2)
  Top 0.12: v32.55,42.43 U430.B9 | U300.A4 57.35,37.71 52.15,32.51 v48.79,32.51 | v48.79,32.51 | v48.79,32.51 48.07,32.51 47.91,32.35 22.51,32.35 13.31,41.55 9.71,41.55 7.35,39.19 7.35,38.59 7.19,38.43 X200.50
  Route3 0.12: v32.55,42.43 32.95,42.03 39.07,42.03 | v48.79,32.51 | v48.79,32.51 48.59,32.51 39.07,42.03 | 39.07,42.03
P0.4  (via drill 0.2)
  Top 0.12: v33.35,42.43 U430.B8 | U300.B5 56.95,41.23 56.95,37.67 | v49.27,32.91 | v49.27,32.91 | v49.27,32.91 52.19,32.91 56.95,37.67 | 56.95,37.67 | v49.27,32.91 | v49.27,32.91 48.11,32.91 47.79,32.59 22.63,32.59 13.43,41.79 9.51,41.79 6.95,39.23 X200.52
  Route3 0.12: 39.03,42.43 v33.35,42.43 | v49.27,32.91 | v49.27,32.91 48.55,32.91 39.03,42.43 | 39.03,42.43 | 39.03,42.43
P0.5  (via drill 0.2)
  Top 0.12: v32.55,43.23 U430.C9 | U300.A5 56.63,40.75 56.63,37.71 56.55,37.63 52.23,33.31 v48.79,33.31 48.15,33.31 47.67,32.83 22.75,32.83 13.55,42.03 8.95,42.03 6.95,40.03 5.35,39.63 X200.54
  Route3 0.12: v32.55,43.23 32.95,42.83 39.07,42.83 | v48.79,33.31 48.59,33.31 39.07,42.83 | 39.07,42.83
P0.6  (via drill 0.2)
  Top 0.12: U300.A6 55.75,38.59 v55.91,38.43
  Bottom 0.12: v55.91,38.43 55.35,38.99 50.95,38.99 50.23,39.71 50.15,39.79 45.99,39.79 45.27,40.51 31.91,40.51 30.55,41.87 24.23,41.87 | 24.23,41.87 10.55,41.95 7.83,39.23 7.83,38.19 7.35,37.71 5.99,37.31 X200.47 | 24.23,41.87 | 24.23,41.87
P0.7  (via drill 0.2)
  Top 0.12: v33.35,44.03 U430.D8 | U300.B7 54.55,41.23 54.55,36.71 52.35,34.51 v49.27,34.51 | v49.27,34.51 | v49.27,34.51 | v49.27,34.51 | v49.27,34.51 48.27,34.51 47.31,33.55 23.11,33.55 13.91,42.75 7.27,42.75 6.23,42.35 4.79,41.95 X200.60 | v49.99,7.95 R410.2 | U500.21 44.71,69.81 44.71,69.47 v45.67,68.51
  Route3 0.12: 39.03,44.03 v33.35,44.03 | v49.27,34.51 | v49.27,34.51 48.55,34.51 39.03,44.03 | 39.03,44.03 | v50.55,23.47 | v50.55,23.47 | v49.11,24.11 49.91,24.11 v50.55,23.47
  Route14 0.12: v49.27,34.51 | v49.27,34.51 | v49.27,34.51 49.75,34.03 49.75,27.39 49.35,26.99 49.35,24.35 v49.11,24.11 | v49.99,7.95 50.31,8.27 50.31,23.23 v50.55,23.47 | v45.67,68.51 35.99,58.83 35.99,49.95 34.95,48.91 34.95,45.63 v33.35,44.03 | v33.35,44.03 | v33.35,44.03
P0.8  (via drill 0.2)
  Top 0.12: v31.75,44.83 U430.E9 | U300.A8 54.15,37.15 54.15,36.67 52.39,34.91 v48.79,34.91 | v48.79,34.91 | v48.79,34.91 48.31,34.91 47.19,33.79 23.23,33.79 14.03,42.99 5.99,42.99 4.55,42.67 X200.62 | R427.2 45.59,31.23 45.99,30.83 v47.91,30.83
  Route3 0.12: v31.75,44.83 32.15,44.43 38.99,44.43 48.51,34.91 v48.79,34.91 | v48.79,34.91
  Route14 0.12: v48.79,34.91 48.31,34.91 47.91,34.51 v47.91,30.83 | v47.91,30.83 | v47.91,30.83
P0.9  (via drill 0.2)
  Top 0.12: v57.75,42.83 | v57.75,42.83 U300.D4 | v46.63,31.31 49.11,31.31 49.27,31.47 52.19,31.47 56.27,35.55 v58.47,35.55
  Route3 0.12: v7.59,41.71 19.83,41.71 23.59,37.95 39.99,37.95 v46.63,31.31
  Route14 0.12: v57.75,42.83 58.15,42.43 58.15,39.55 59.03,38.67 59.03,36.11 v58.47,35.55
  Bottom 0.12: v7.59,41.71 6.95,42.35 6.15,42.35 4.79,41.95 X200.59
P0.10  (via drill 0.2)
  Top 0.12: v57.75,41.23 U300.B4 | 37.26,62.02 37.27,62.03 v37.43,61.87
  Top 0.2: C417.1 R430.1 SW402.P1 37.26,62.02 SW402.P | SW402.P | SW402.P
  Route14 0.12: v57.75,41.23 57.75,33.07 57.75,29.39 58.07,29.07 v58.07,27.87 | v57.75,41.23 | v58.07,27.87 | v58.07,27.87 | v18.71,34.35 19.11,34.75 21.91,34.75 23.67,36.51 23.67,37.47 26.71,40.51 29.11,40.51 29.67,41.07 29.67,46.43 29.19,46.91 29.19,52.27 28.71,52.75 28.71,55.39 30.39,57.07 31.59,57.07 33.91,59.39 35.35,59.39 37.43,61.47 v37.43,61.87 | v58.07,27.87
  Bottom 0.12: v58.07,27.87 58.07,27.71 57.11,26.75 52.39,26.75 51.99,27.15 37.75,27.15 31.27,33.63 19.43,33.63 v18.71,34.35
P0.11  (via drill 0.2)
  Top 0.12: v56.95,43.63 | v56.95,43.63 U300.E5 | X200.20 11.11,23.79 11.75,23.79 v12.07,24.11
  Route3 0.12: v56.95,43.63 56.55,43.23 56.55,38.07 56.31,37.83 56.31,28.51 v55.83,28.03 | v12.07,24.11 12.71,23.47 14.07,23.47 14.95,24.35 23.03,24.35 23.51,24.83 50.63,24.83 51.59,25.79 v55.83,25.79 | v55.83,25.79 | v55.83,25.79
  Route14 0.12: v55.83,25.79 | v55.83,25.79 | v55.83,25.79 v55.83,28.03 | v55.83,25.79
P0.12  (via drill 0.2)
  Top 0.12: v56.95,42.83 U300.D5
  Route3 0.12: v56.95,42.83 57.35,42.43 57.35,41.71 57.11,41.47 57.11,32.67 | 56.71,32.27 56.71,28.19 56.15,27.63 54.71,27.63 54.31,28.03 32.67,28.03 31.15,26.51 23.83,26.51 23.27,27.07 15.43,27.07 v14.95,26.59 | 57.11,32.67 | 57.11,32.67 | 56.71,32.27 | 56.71,32.27 57.11,32.67
  Bottom 0.12: 14.95,20.51 12.87,18.43 11.19,17.95 X200.5 | v14.95,26.59 14.95,24.83 15.59,24.19 15.59,23.39 14.95,22.75 14.95,20.51 | 14.95,20.51
P0.13  (via drill 0.2)
  Top 0.12: v56.95,42.03 | v56.95,42.03 U300.C5 | v70.71,29.23 78.31,21.63 78.31,20.51 79.99,18.83 79.96,18.83 X202.30 | U302.6 18.47,30.19 17.35,30.19 15.91,28.75 v15.91,26.35
  Route3 0.12: v70.71,29.23 69.35,29.23 69.19,29.07 64.79,29.07 63.11,27.39 v56.55,27.39 54.55,27.39 54.15,27.79 32.79,27.79 31.27,26.27 23.67,26.27 23.11,26.83 16.39,26.83 v15.91,26.35
  Route14 0.12: v56.95,42.03 56.95,32.59 56.95,27.79 | v56.55,27.39 | 56.95,27.79 | v56.55,27.39 56.95,27.79
  Bottom 0.12: X200.3 12.79,17.63 15.91,20.75 15.91,22.91 16.07,23.07 16.07,24.51 15.91,24.67 v15.91,26.35
P0.14  (via drill 0.2)
  Top 0.12: v56.15,43.63 | v56.15,43.63 U300.E6 | v56.15,43.63 | X200.10 10.79,19.47 12.23,19.95 13.43,19.95 13.99,20.51 13.99,20.91 16.31,23.23 16.47,23.39 16.47,26.67 16.31,26.83 16.31,28.59 16.63,28.91 R303.1 17.27,28.91 | 17.27,28.91 | 17.27,28.91 17.43,29.07 17.83,29.07 U302.7 20.23,28.43 22.07,28.43 v22.63,28.99
  Route3 0.12: v56.15,43.63 55.91,43.63 55.59,43.31 55.59,38.99 55.27,38.67 | v22.63,28.99 54.87,28.99 55.27,29.39 55.27,38.67 | 55.27,38.67
P0.15  (via drill 0.2)
  Top 0.12: v56.15,42.03 | v56.15,42.03 U300.C6 | X200.8 13.43,19.39 14.23,20.19 14.23,20.75 16.55,23.07 18.23,24.75 20.99,24.75 24.43,28.19 25.51,28.19 26.55,28.03 | 26.55,28.03 U302.3 | 26.55,28.03 R310.1 28.39,27.47 v28.63,28.43
  Route3 0.12: v56.15,42.03 56.15,38.83 56.31,38.67 56.31,38.19 56.07,37.95 56.07,29.83 54.99,28.75 28.95,28.75 v28.63,28.43
P1.0  (via drill 0.2)
  Top 0.12: v52.95,42.83 | v52.95,42.83 U300.D9 | v39.11,30.11 48.71,30.11 48.87,30.27 v51.11,30.27
  Route14 0.12: v52.95,42.83 52.55,42.43 52.55,37.63 51.11,36.19 v51.11,30.27 | v39.11,30.11 39.11,30.51 38.95,30.67 38.95,43.63 41.35,46.03 41.35,60.51 43.99,63.15 43.99,63.79 44.79,64.59 46.23,64.59 47.43,65.79 47.43,70.75 46.15,72.03 46.15,74.27 | v44.87,82.19 | 46.15,74.27 47.03,75.15 47.03,79.47 44.87,81.63 v44.87,82.19 | 46.15,74.27
  Bottom 0.12: v44.87,82.19 44.87,82.23 43.59,83.51 43.59,85.39 43.83,86.83 X201.9
P1.1  (via drill 0.2)
  Top 0.12: v52.95,43.63 | U300.E9 v52.95,43.63 | V301.C v41.11,63.15
  Route3 0.12: v51.91,69.07 49.51,69.07 v47.91,67.47 45.43,67.47 v41.11,63.15
  Route14 0.12: v52.95,43.63 | v52.95,43.63 U300.E9 53.35,46.27 53.51,46.43 53.99,46.43 54.15,46.59 54.15,52.75 52.71,54.19 52.71,59.31 52.31,59.71 52.31,68.59 51.91,68.99 v51.91,69.07
  Bottom 0.12: X201.11 44.63,86.67 44.31,85.23 44.31,83.47 45.27,82.51 45.27,77.87 44.79,77.39 44.79,77.07 44.07,76.35 43.75,76.35 43.51,76.11 43.51,74.99 45.67,72.83 45.67,70.35 | v47.91,67.47 47.91,67.71 45.67,69.95 45.67,70.35 | 45.67,70.35
P1.2  (via drill 0.2)
  Top 0.12: U300.C11 51.35,42.83 50.15,42.83 49.59,42.27 v45.99,42.27 45.27,42.27 44.71,41.71 40.83,41.71 39.71,42.83 U430.B1 | v43.43,35.63 43.27,35.47 24.07,35.47 14.87,44.67 9.67,44.67 5.83,48.51 4.55,48.51 3.11,48.11 X200.76
  Route14 0.12: v45.99,42.27 | 45.99,40.67 v45.99,42.27 | 45.99,40.67 | v43.43,35.63 45.99,38.19 45.99,40.67
P1.3  (via drill 0.2)
  Top 0.12: U300.C12 50.15,42.43 49.75,42.03 46.71,42.03 46.47,41.79 v45.59,41.79 | U430.A2 38.15,42.43 39.75,42.43 40.71,41.47 45.27,41.47 v45.59,41.79 | v43.43,36.27 42.87,35.71 24.19,35.71 14.99,44.91 9.79,44.91 5.47,49.23 4.31,49.23 2.87,48.91 X200.78 | v45.59,41.79
  Route14 0.12: v45.59,41.79 | 45.59,41.15 v45.59,41.79 | 45.59,41.15 | v43.43,36.27 45.59,38.43 45.59,41.15
P1.4  (via drill 0.2, 0.2 pad 0.55)
  Top 0.12: v32.45,14.91 32.47,14.91 X401.D2 32.95,16.51 35.27,16.51 37.91,19.15 38.84,19.15 U301.2 | U500.45 37.19,73.79 v37.19,74.83
  Top 0.127: v52.15,42.03 U300.C10
  Route3 0.12: v52.15,42.03 52.15,33.55 48.07,29.47 34.63,29.47 | v34.47,29.63 | 34.63,29.47 | v34.47,29.63 34.63,29.47
  Route14 0.12: v32.45,14.91 33.91,16.37 33.91,29.07 v34.47,29.63 33.91,30.19 33.91,36.99 34.95,38.03 34.95,44.83 35.43,45.31 35.43,48.59 36.47,49.63 36.47,56.67 37.67,57.87 v37.67,58.43
  Bottom 0.12: v37.67,58.43 37.27,58.83 36.63,58.83 33.03,62.43 33.03,70.27 36.63,73.87 36.95,73.87 37.19,74.11 v37.19,74.83
P1.5  (via drill 0.2)
  Top 0.12: v31.19,15.07 31.67,16.83 X401.D4 31.75,16.82 31.75,16.83 31.83,16.91 31.83,17.39 32.55,18.11 32.95,18.11 34.95,17.55 35.91,17.55 39.59,21.23 40.95,21.23 U306.2 | U500.46 36.71,73.56 v36.71,74.35
  Top 0.127: v52.15,42.83 U300.D10
  Route3 0.12: v52.15,42.83 | 35.19,29.71 47.91,29.71 51.75,33.55 51.75,39.15 51.35,39.55 51.35,42.03 v52.15,42.83 | 35.19,29.71 34.79,30.11 34.15,30.11 v33.67,29.63 | 35.19,29.71 | v33.67,29.63
  Route14 0.12: v31.19,15.07 33.67,17.55 v33.67,29.63 33.67,37.15 34.71,38.19 34.71,44.99 35.19,45.47 35.19,48.75 36.23,49.79 36.23,57.23 v37.03,58.03
  Bottom 0.12: v37.03,58.03 32.79,62.27 32.79,70.43 v36.71,74.35
P1.6  (via drill 0.2)
  Top 0.12: v41.19,44.43 U430.D1 | U300.B9 52.95,41.23 52.95,38.67 53.07,38.55 53.07,36.67 52.47,36.11 48.63,36.11 v47.75,36.99 | 4.16,45.05 3.91,44.99 | 4.16,45.05 4.55,45.15 | v45.43,34.67 45.27,34.51 23.59,34.51 14.39,43.71 9.19,43.71 7.75,45.15 7.51,45.39 5.35,45.39 3.91,44.99 | v47.75,36.99 | X200.68 3.91,44.99 | 4.16,45.05 4.15,45.07 3.91,44.99
  Route3 0.12: v47.75,36.99 47.51,36.99 41.19,43.31 v41.19,44.43 | v41.19,44.43
  Route14 0.12: v47.75,36.99 | v45.43,34.67 v47.75,36.99
P1.7  (via drill 0.2)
